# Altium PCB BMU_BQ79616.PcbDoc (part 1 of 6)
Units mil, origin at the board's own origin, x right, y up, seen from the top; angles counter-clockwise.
Board outline 7605 x 4005 mil, 4 copper layers (Top Layer, Layer 1, Layer 2, Bottom Layer), stack 37.446 mil thick; 709 components, 447 nets, 2028 pads, 1862 vias.
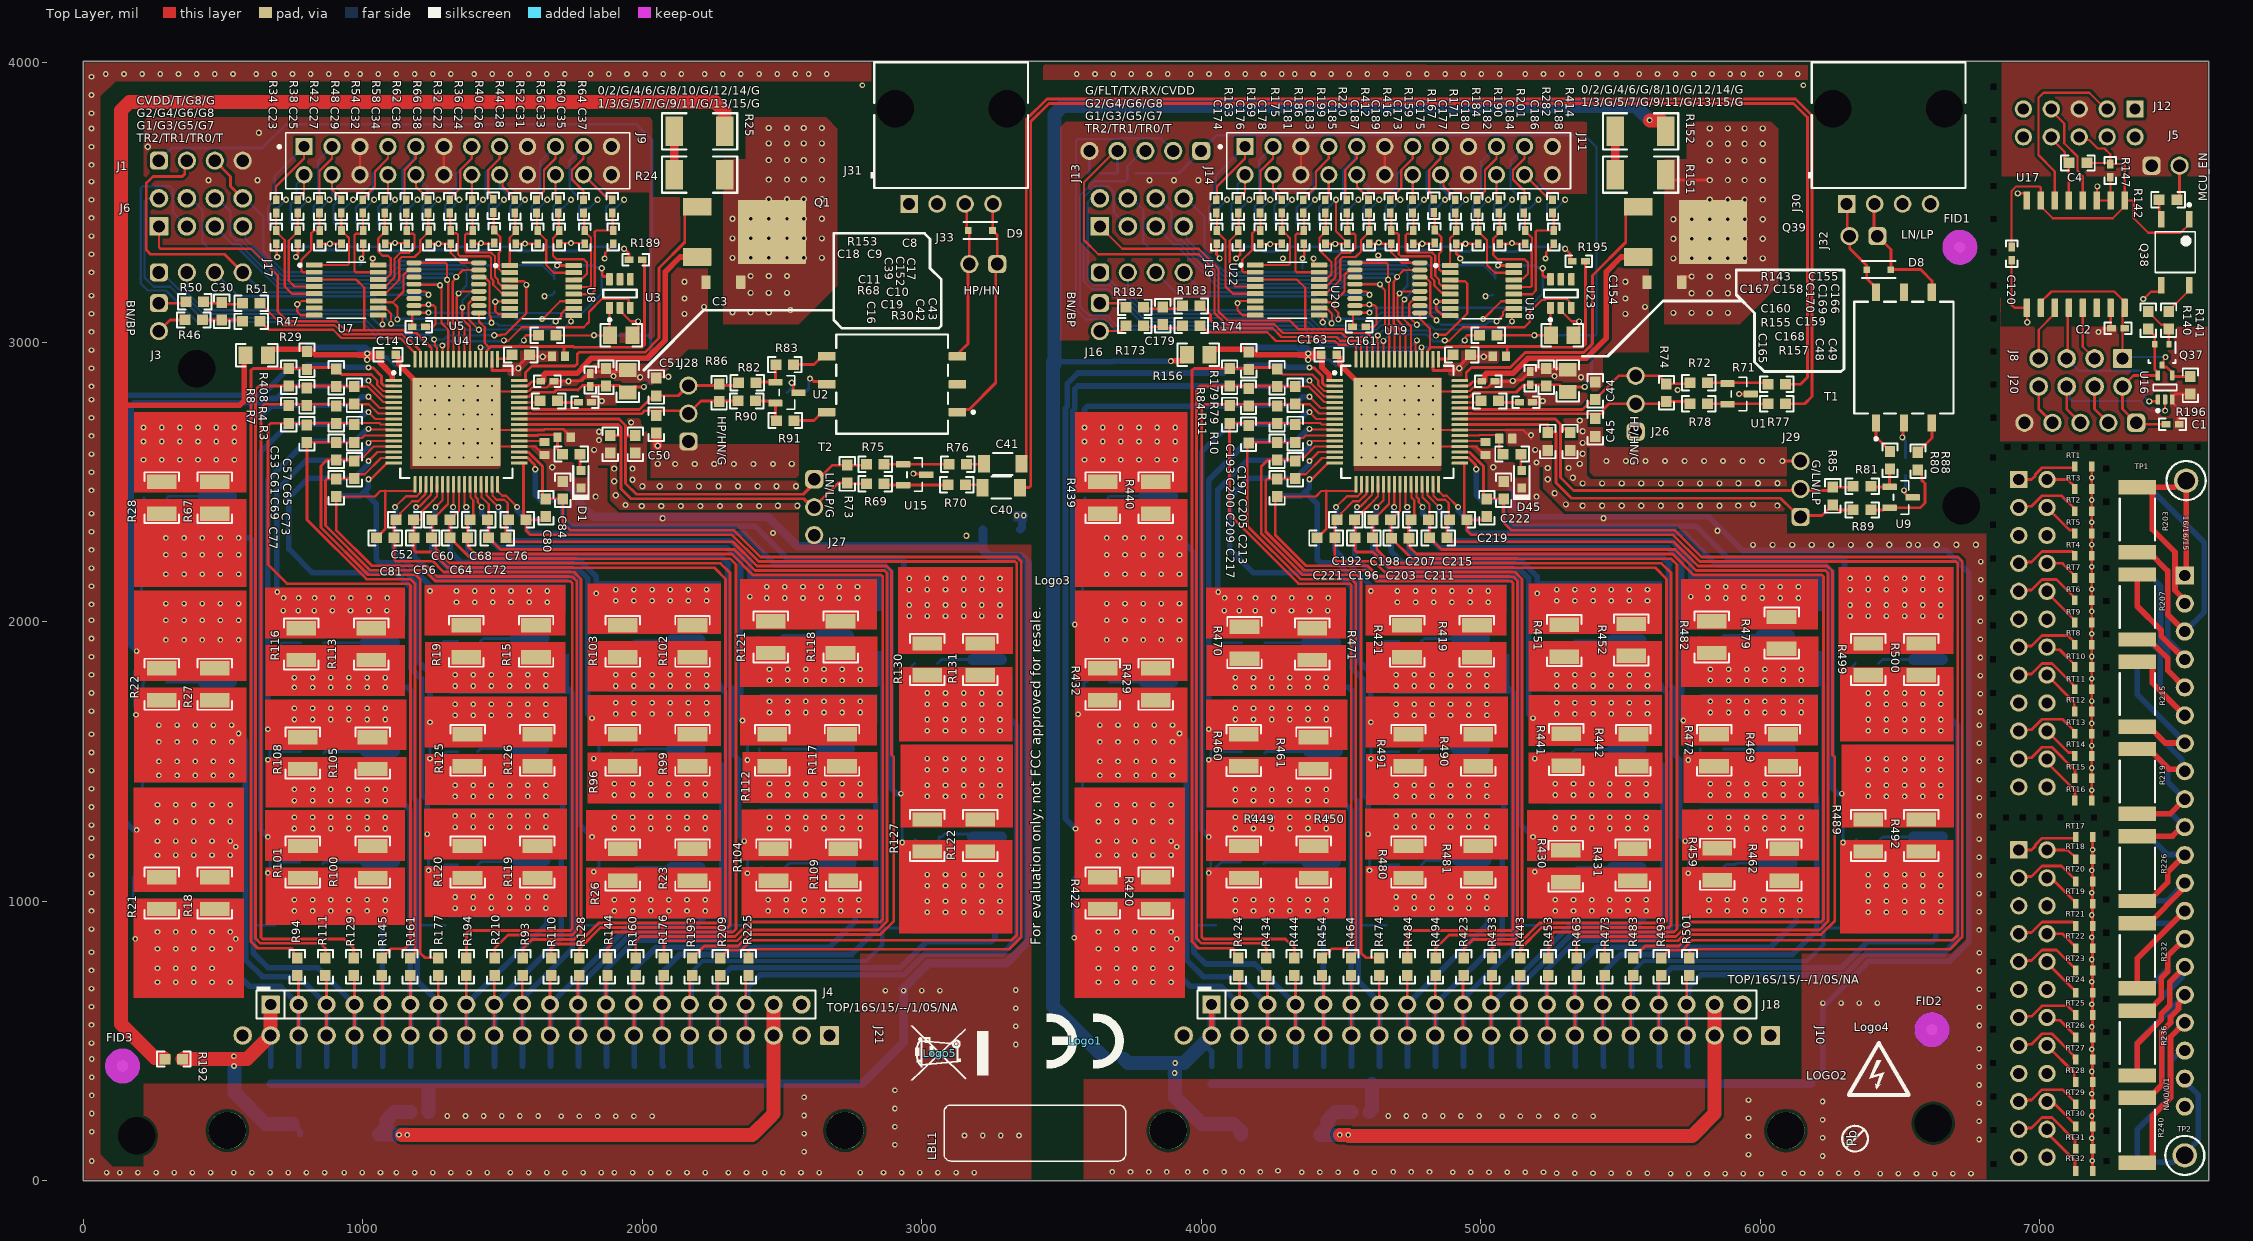
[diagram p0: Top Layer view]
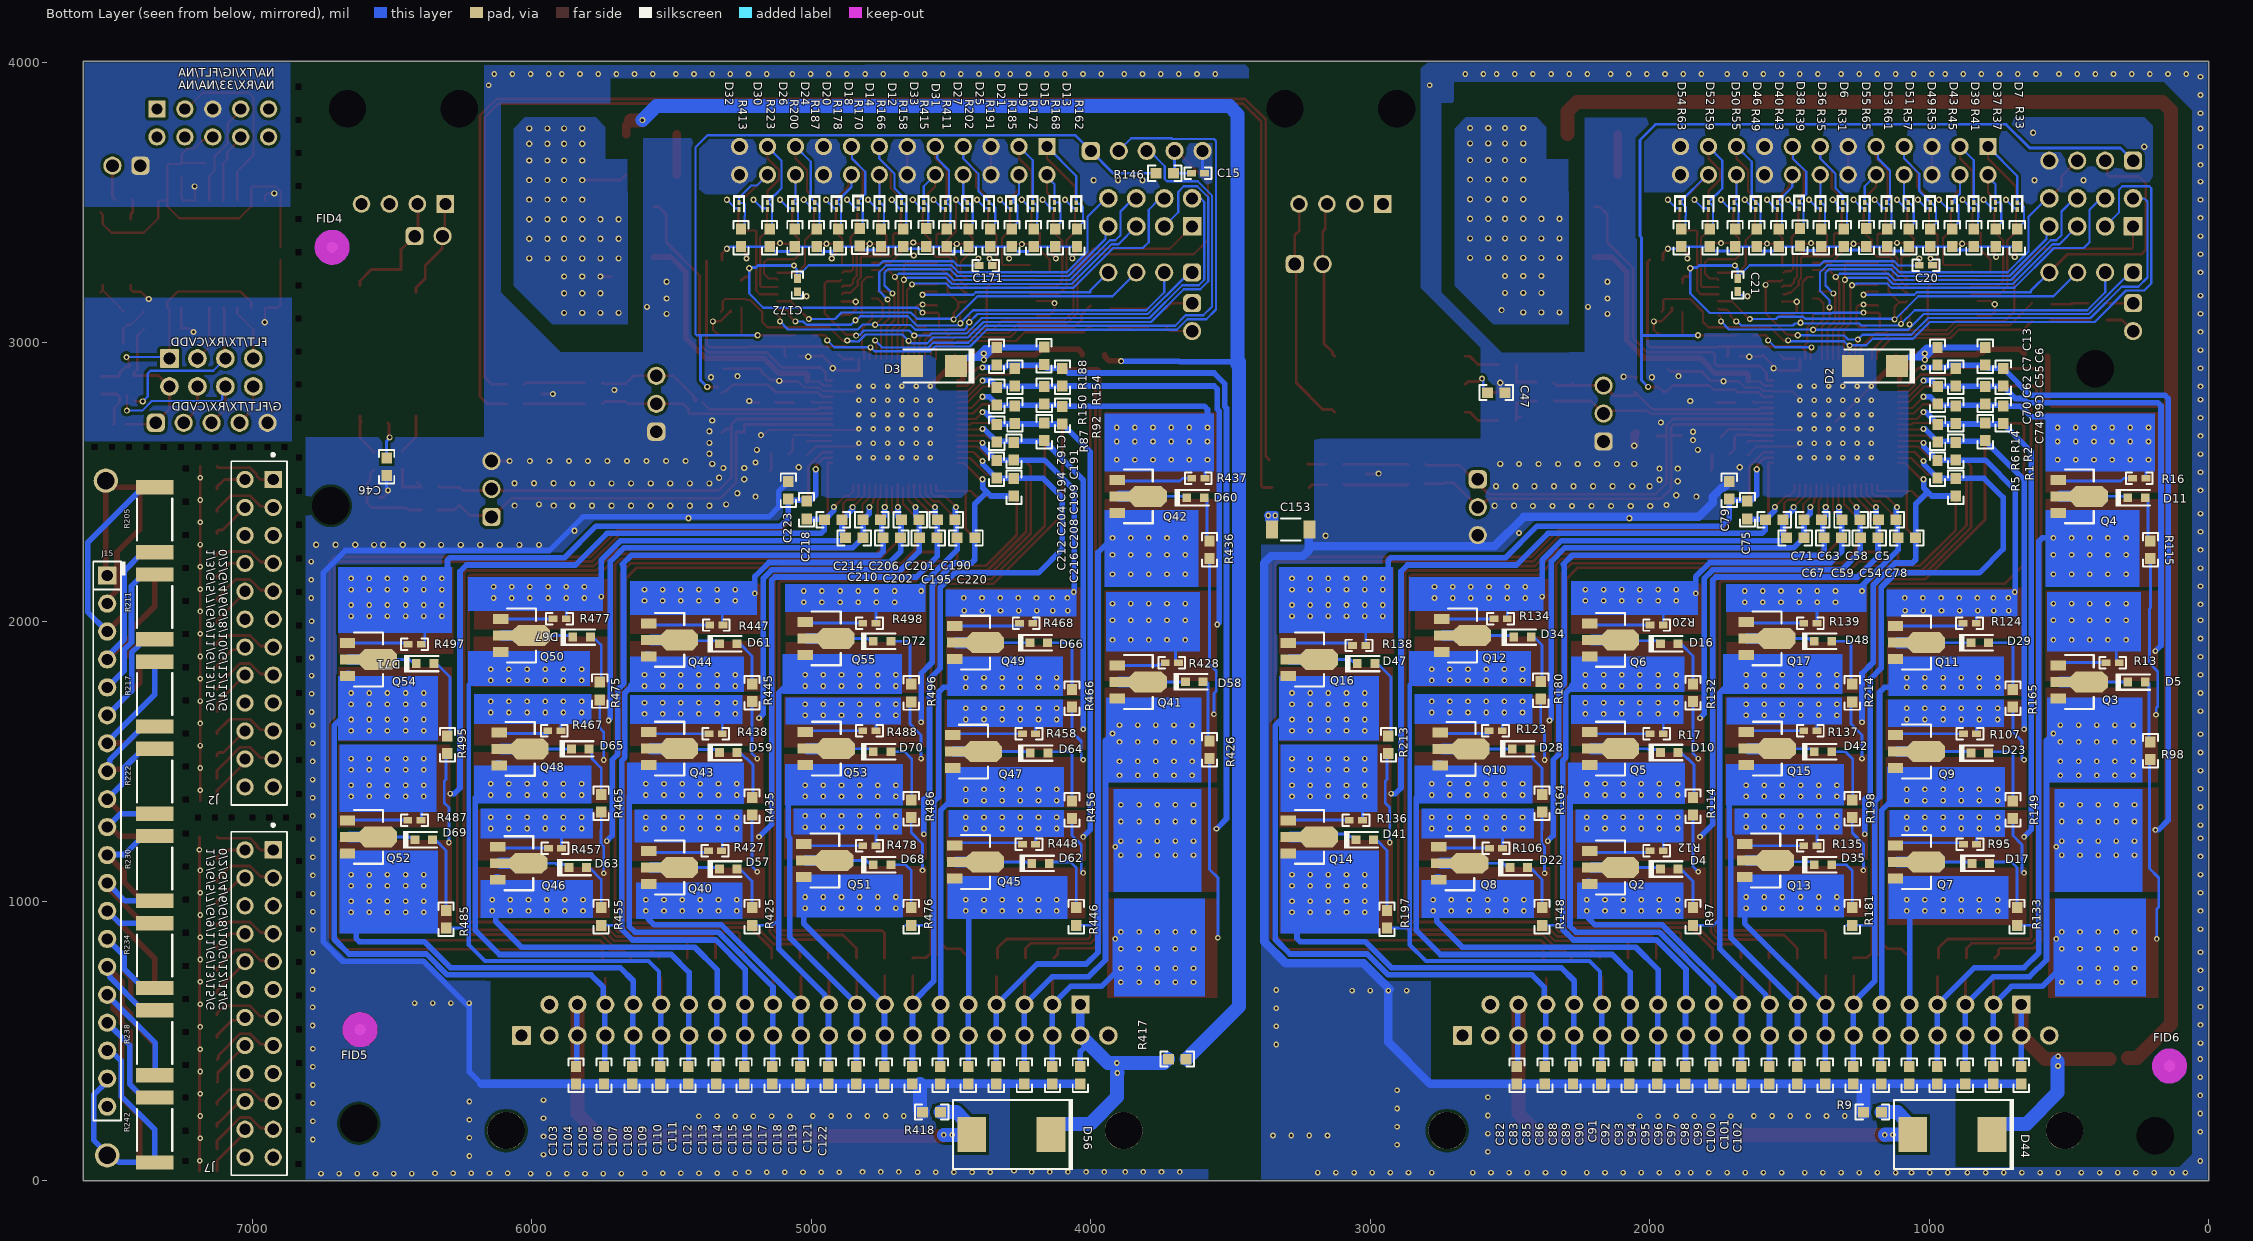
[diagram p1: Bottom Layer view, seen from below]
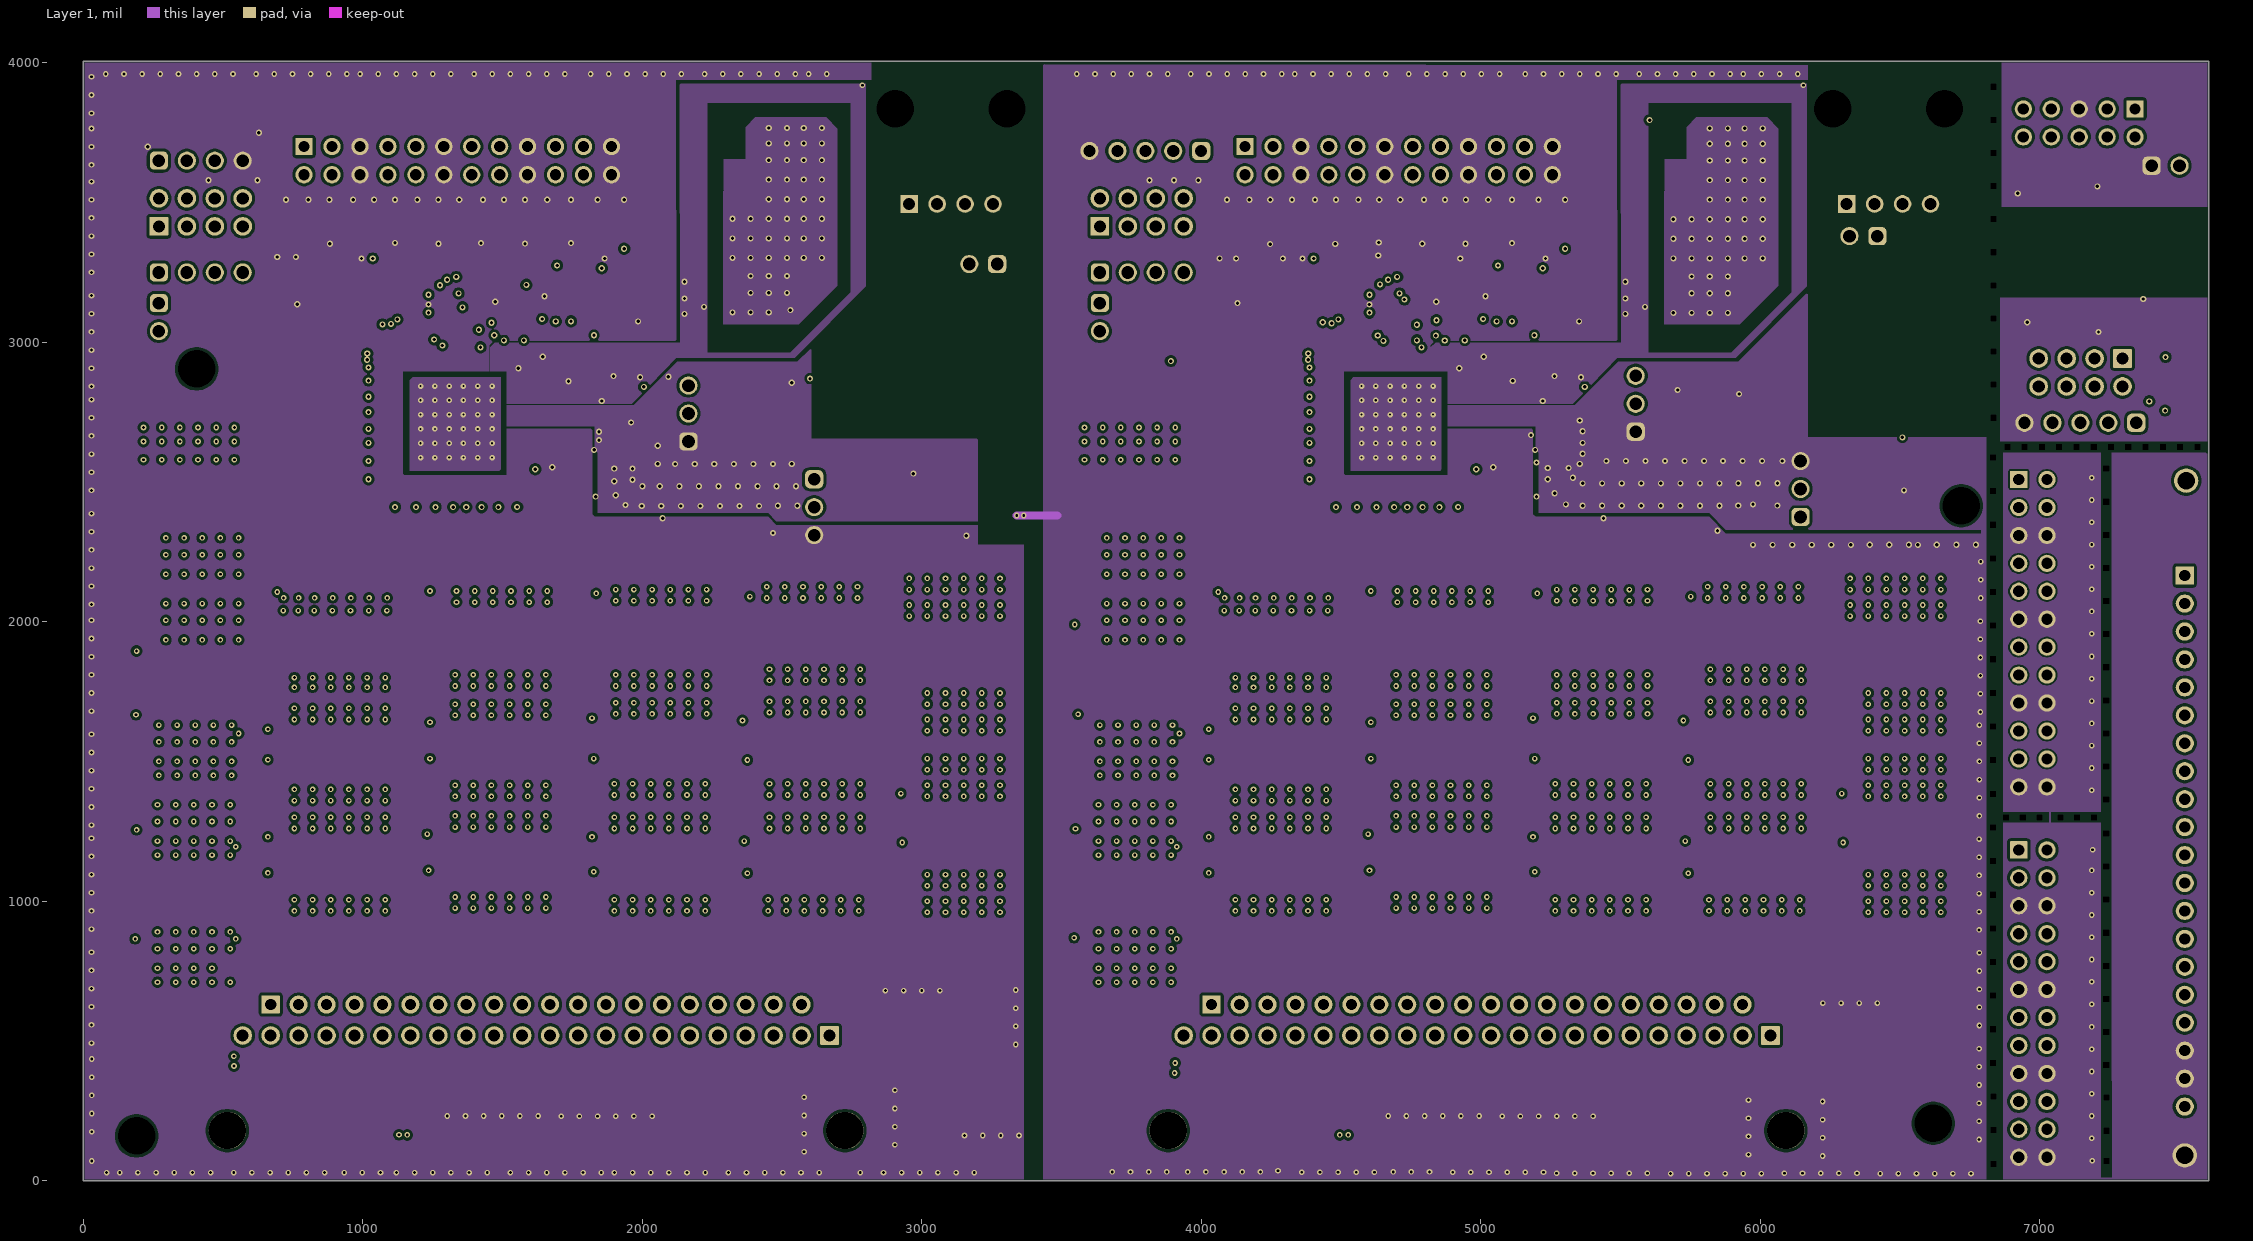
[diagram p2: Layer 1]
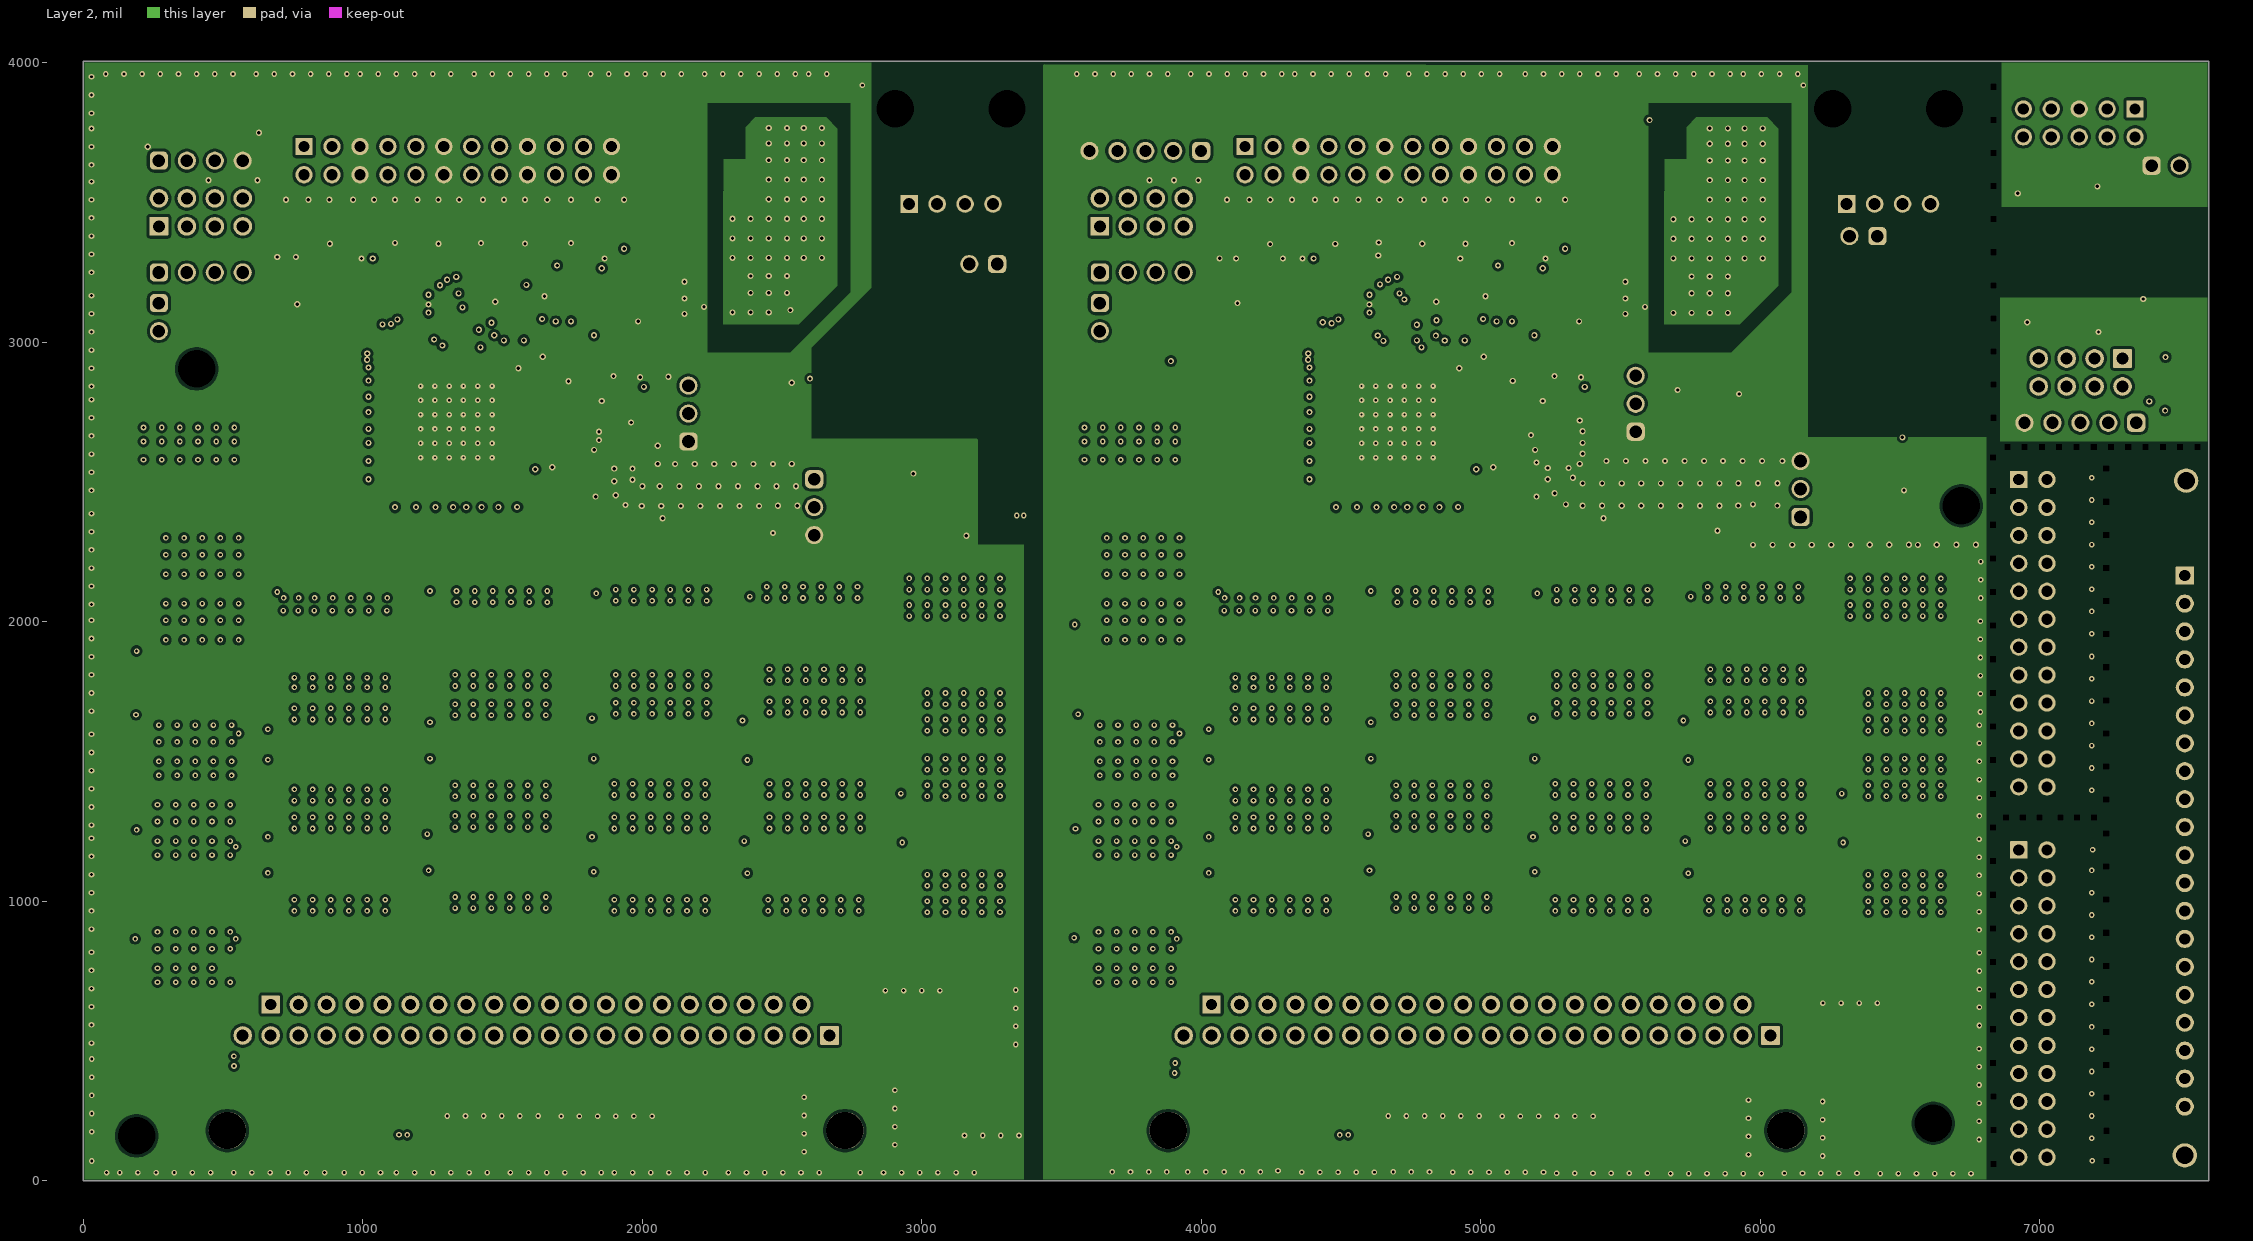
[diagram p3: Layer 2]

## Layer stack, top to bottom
Top Solder: solder mask 0.4, Solder Resist, Dk 3.5
Top Layer: signal copper 1.4
Dielectric 2: prepreg 6.693, PP-006, Dk 4.1
Layer 1: signal copper 1.378
Dielectric 1: prepreg 18.504, FR-4, Dk 4.8
Layer 2: signal copper 1.378
Dielectric 3: prepreg 6.693, PP-006, Dk 4.1
Bottom Layer: signal copper 1.4
Bottom Solder: solder mask 0.4, Solder Resist, Dk 3.5

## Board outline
6825,4005 7605,4005 7605,2640 7605,0 0,0 0,4005

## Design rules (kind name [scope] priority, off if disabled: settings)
AcuteAngle [All] p1: minimum=4.50000000000000E+0001 checktracksonly=FALSE
AssemblyTestPointUsage [All] p1: valid=2
BoardOutlineClearance BoardOutlineClearance_MountingHoles [OnCopper and InComponentClass('Mounting Holes')] p1: gap=39.37 ignorepadtopadclearanceinfootprint=FALSE
BoardOutlineClearance BoardOutlineClearance_Poly [OnCopper and IsPoly] p2: gap=3.94 ignorepadtopadclearanceinfootprint=FALSE
BoardOutlineClearance [OnCopper and Not InComponentClass('Logo') and not InComponentClass('FiducialMark') and not InRegion(1000,500,4000,800) and not InPoly] p3: gap=3.94 ignorepadtopadclearanceinfootprint=FALSE
Clearance Clearance_Fid [InComponent('FID1') or InComponent('FID2') or InComponent('FID3') or InComponent('FID4') or InComponent('FID5') or InComponent('FID6')] p1: gap=0 ignorepadtopadclearanceinfootprint=TRUE
Clearance Clearance_J2 [InComponent('J2')] p2: gap=6 ignorepadtopadclearanceinfootprint=TRUE
Clearance Clearance_Inner1 [OnLayer('Top Inner')] p3: gap=6 ignorepadtopadclearanceinfootprint=TRUE except(15: Arc-Fill Arc-Poly Arc-Region Track-Fill Track-Poly Track-Region SMDPad-Fill SMDPad-Poly SMDPad-Region THPad-Fill THPad-Poly THPad-Region Via-Fill Via-Poly Via-Region Fill-Fill Fill-Poly Fill-Region Poly-Poly Poly-Region Region-Region)
Clearance Clearance_Inner2 [OnLayer('Bottom Inner')] p4: gap=6 ignorepadtopadclearanceinfootprint=TRUE except(15: Arc-Fill Arc-Poly Arc-Region Track-Fill Track-Poly Track-Region SMDPad-Fill SMDPad-Poly SMDPad-Region THPad-Fill THPad-Poly THPad-Region Via-Fill Via-Poly Via-Region Fill-Fill Fill-Poly Fill-Region Poly-Poly Poly-Region Region-Region)
Clearance [All] p5: gap=6 ignorepadtopadclearanceinfootprint=TRUE except(10: Arc-Fill Arc-Poly Arc-Region Track-Fill Track-Poly Track-Region SMDPad-Fill SMDPad-Poly SMDPad-Region THPad-Fill THPad-Poly THPad-Region Via-Fill Via-Poly Via-Region Fill-Fill Fill-Poly Fill-Region Poly-Poly Poly-Region Region-Region)
ComponentClearance ComponentClearance_Header [InComponent('J17') or InComponent('J19') or InComponent('J23')] p1: gap=0.39 collisioncheckmode=3 verticalgap=0.39 showdistances=FALSE
ComponentClearance ComponentClearance_MountingHoles_FiducialMarks [InComponentClass('Mounting Holes') vs InComponentClass('FiducialMark')] p2: gap=50 collisioncheckmode=3 verticalgap=10 showdistances=FALSE
ComponentClearance ComponentClearance_Shunt [InComponentClass('Header') vs InComponentClass('Shunt')] p3: gap=0 collisioncheckmode=3 verticalgap=0 showdistances=FALSE
ComponentClearance ComponentClearance_Logo [InComponentClass('Logo')] p4: gap=50 collisioncheckmode=3 verticalgap=10 showdistances=FALSE
ComponentClearance ComponentClearance_ScrewToNut [(HasFootprint('NY PMS 440 0025 PH')) vs (HasFootprint('Keystone_1902C'))] p5: gap=5 collisioncheckmode=3 verticalgap=10 showdistances=FALSE
ComponentClearance ComponentClearance_MountingHoles [InComponentClass('Mounting Holes')] p6: gap=250 collisioncheckmode=3 verticalgap=100000 showdistances=FALSE
ComponentClearance ComponentClearance_SmallPassives [HasFootprint('0201*') or HasFootprint('0402*') or HasFootprint('0508') or HasFootprint('0603*') or HasFootprint('0612') or HasFootprint('0805*') or HasFootprint('0815*') or HasFootprint('0830*') or HasFootprint('1206*') or HasFootprint('1210*') or HasFootprint('1808*') or HasFootprint('1812*') or HasFootprint('1825*') or HasFootprint('2010*') or HasFootprint('2220*') or HasFootprint('2225*') or HasFootprint('2512*') or HasFootprint('2728*') or HasFootprint('3518*') vs HasFootprint('0201*') or HasFootprint('0402*') or HasFootprint('0508') or HasFootprint('0603*') or HasFootprint('0612') or HasFootprint('0805*') or HasFootprint('0815*') or HasFootprint('0830*') or HasFootprint('1206*') or HasFootprint('1210*') or HasFootprint('1808*') or HasFootprint('1812*') or HasFootprint('1825*') or HasFootprint('2010*') or HasFootprint('2220*') or HasFootprint('2225*') or HasFootprint('2512*') or HasFootprint('2728*') or HasFootprint('3518*')] p7: gap=0.39 collisioncheckmode=3 verticalgap=10 showdistances=FALSE
ComponentClearance ComponentClearance_THtoSMT [IsThruComponent vs IsSMTComponent] p8: gap=40 collisioncheckmode=3 verticalgap=30 showdistances=FALSE
ComponentClearance ComponentClearance_THtoTH [IsThruComponent vs IsThruComponent] p9: gap=30 collisioncheckmode=3 verticalgap=30 showdistances=FALSE
ComponentClearance [All] p10: gap=0 collisioncheckmode=3 verticalgap=10 showdistances=FALSE
DiffPairsRouting [All] p1: maxlimit=100 minlimit=10 mostfreqgap=10 toplayer_minwidth=7.87 toplayer_maxwidth=15 toplayer_prefwidth=10 midlayer1_minwidth=7.87 midlayer1_maxwidth=15 midlayer1_prefwidth=10 midlayer2_minwidth=7.87 midlayer2_maxwidth=15 midlayer2_prefwidth=10 bottomlayer_minwidth=7.87 bottomlayer_maxwidth=15 bottomlayer_prefwidth=10 maxuncoupledlength=1000
FabricationTestPointUsage TestPointUsage [All] p1: valid=2 allowmultiple=FALSE
FabricationTestpoint Testpoint [All] p1: side=3 testpointundercomponent=TRUE minsize=40 maxsize=100 preferedsize=60 minholesize=0 maxholesize=40 preferedholesize=32 testpointgrid=1 allowsidetop=TRUE allowsidebottom=TRUE usegrid=TRUE gridtolerance=0.01
FanoutControl Fanout_LCC [IsLCC] p1: bgadir=Out bgaviamode=Centered fanoutstyle=Auto fanoutdirection=Alternating viagrid=1 // Fanout_LCC (Default Rule)
FanoutControl Fanout_BGA [IsBGA] p2: bgadir=Out bgaviamode=Centered fanoutstyle=Auto fanoutdirection=Alternating viagrid=1 // Fanout_BGA (Default Rule)
FanoutControl Fanout_Default [All] p4: bgadir=Out bgaviamode=Centered fanoutstyle=Auto fanoutdirection=Alternating viagrid=1 // Fanout_Default (Default Rule)
FanoutControl Fanout_Small [(CompPinCount < 5)] p5: bgadir=Out bgaviamode=Centered fanoutstyle=Auto fanoutdirection=OutThenIn viagrid=1 // Fanout_Small (Default Rule)
Height [All] p1: minheight=0 maxheight=2048 prefheight=500
HoleSize [All] p1: absolutevalues=TRUE maxlimit=251 minlimit=7.87 maxpercent=80.000 minpercent=20.000
HoleToHoleClearance [All] p1: gap=7.87 allowstackedmicrovias=TRUE
MinimumAnnularRing MinimumAnnularRing_ThermalPadVias [IsVia and InAnyComponent] p1: minimumring=2
MinimumAnnularRing [All] p2: minimumring=3.94
MinimumSolderMaskSliver MinimumSolderMaskSliver_Logo [InComponentClass('Logo') vs InComponentClass('Logo')] p1: minsoldermaskwidth=0.7
MinimumSolderMaskSliver [All] p2: minsoldermaskwidth=0.39
PlaneConnect [All] p1: planeconnectstyle=Relief reliefexpansion=10 reliefentries=4 reliefconductorwidth=10 reliefairgap=10
PolygonConnect [All] p1: connectstyle=Direct reliefconductorwidth=10 reliefentries=4 polygonreliefangle="90 Angle" airgapwidth=10
RoutingVias ThermalPadVias [IsVia and InAnyComponent] p1: holewidth=7.87 width=19.68 viastyle="Through Hole" minholewidth=7.87 minwidth=11.81 maxholewidth=19.68 maxwidth=27.56
RoutingVias [All] p2: holewidth=16 width=34 viastyle="Through Hole" minholewidth=7.87 minwidth=15 maxholewidth=40 maxwidth=65
SilkToSilkClearance SilkToSilkClearance_Pb-FreeLogo [(HasFootprint('Pb-Free_Overlay_Medium') OR HasFootprint('Pb-Free_Overlay_Small')) vs (HasFootprint('Pb-Free_Overlay_Medium') OR HasFootprint('Pb-Free_Overlay_Small'))] p1: silktosilkclearance=0
SilkToSilkClearance [All] p2: silktosilkclearance=0.39
SilkToSolderMaskClearance SilkToComponentPadClearance [(IsPad or IsFill or IsRegion) and InAnycomponent] p1: minsilkscreentomaskgap=0 clearancetoexposedcopper=TRUE
SilkToSolderMaskClearance "Silk to Solder Mask Opening" [All] p2: minsilkscreentomaskgap=0 clearancetoexposedcopper=FALSE
SolderMaskExpansion [All] p1: expansion=1.97 istentingtop=FALSE
UnRoutedNet [All] p1: checkbadconnections=TRUE
Width [All] p1: maxlimit=100 minlimit=99999 preferedwidth=10 toplayer_minwidth=0 midlayer1_minwidth=0 midlayer2_minwidth=0 bottomlayer_minwidth=0 minimp=50.000000 maximp=50.000000 favimp=50.000000 checkconnectedcopper=TRUE
13 further rules are at their usual default settings.

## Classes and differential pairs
component class U_Cell_Simulator: J2 J7 J15 R203 R205 R207 R211 R215 R217 R219 R222 R226 R230 R232 R234 R236 R238 R240 R242 RT1 RT2 RT3 RT4 RT5 RT6 RT7 RT8 RT9 RT10 RT11 RT12 RT13 RT14 RT15 RT16 RT17 RT18 RT19 RT20 RT21 RT22 RT23 RT24 RT25 RT26 RT27 RT28 RT29 RT30 RT31 RT32 TP1 TP2
component class "Transf_Daisy Chain Isolation": C46 C47 C48 C49 C50 C51 D8 D9 J28 J29 J30 J31 J32 J33 R80 R81 R82 R83 R85 R86 R88 R89 R90 R91 T1 T2 U2 U9
component class Label: LBL1
component class Header: J1 J3 J4 J5 J13 J15 J16 J17 J18 J19 J20 J26 J27 J28 J29 J32 J33
component class Hardware: !PCB1 FID1 FID2 FID3 FID4 FID5 FID6 H9 H10 H11 LBL1 LOGO2 Logo3 Logo4
component class FiducialMark: FID1 FID2 FID3 FID4 FID5 FID6
component class Cell_Network_A2: C5 C6 C7 C52 C53 C54 C55 C56 C57 C58 C59 C60 C61 C62 C63 C64 C65 C66 C67 C68 C69 C70 C71 C72 C73 C74 C75 C76 C77 C78 C79 C80 C81 C82 C83 C84 C85 C86 C88 C89 C90 C91 C92 C93 C94 C95 C96 C97 C98 C99 C100 C101 C102 D4 D5 D10 D11 D16 D17 D22 D23 D28 D29 D34 D35 D41 D42 D44 D47 D48 J3 J4 J21 Q2 Q3 Q4 Q5 Q6 Q7 Q8 Q9 Q10 Q11 Q12 Q13 Q14 Q15 Q16 Q17 R9 R12 R13 R15 R16 R17 R18 R19 R20 R21 R22 R23 R26 R27 R28 R67 R93 R94 R95 R96 R97 R98 R99 R100 R101 R102 R103 R104 R105 R106 R107 R108 R109 R110 R111 R112 R113 R114 R115 R116 R117 R118 R119 R120 R121 R122 R123 R124 R125 R126 R127 R128 R129 R130 R131 R132 R133 R134 R135 R136 R137 R138 R139 R144 R145 R148 R149 R160 R161 R164 R165 R176 R177 R180 R181 R192 R193 R194 R197 R198 R209 R210 R213 R214 R225
component class Cell_Network_A1: C103 C104 C105 C106 C107 C108 C109 C110 C111 C112 C113 C114 C115 C116 C117 C118 C119 C121 C122 C190 C191 C192 C193 C194 C195 C196 C197 C198 C199 C200 C201 C202 C203 C204 C205 C206 C207 C208 C209 C210 C211 C212 C213 C214 C215 C216 C217 C218 C219 C220 C221 C222 C223 D56 D57 D58 D59 D60 D61 D62 D63 D64 D65 D66 D67 D68 D69 D70 D71 D72 J10 J16 J18 Q40 Q41 Q42 Q43 Q44 Q45 Q46 Q47 Q48 Q49 Q50 Q51 Q52 Q53 Q54 Q55 R417 R418 R419 R420 R421 R422 R423 R424 R425 R426 R427 R428 R429 R430 R431 R432 R433 R434 R435 R436 R437 R438 R439 R440 R441 R442 R443 R444 R445 R446 R447 R448 R449 R450 R451 R452 R453 R454 R455 R456 R457 R458 R459 R460 R461 R462 R463 R464 R465 R466 R467 R468 R469 R470 R471 R472 R473 R474 R475 R476 R477 R478 R479 R480 R481 R482 R483 R484 R485 R486 R487 R488 R489 R490 R491 R492 R493 R494 R495 R496 R497 R498 R499 R500 R501
component class "Cap_Daisy Chain Isolation": C40 C41 C42 C43 C44 C45 C153 J26 J27 R69 R70 R71 R72 R73 R74 R75 R76 R77 R78 U1 U15
component class bq79616_A2: C3 C8 C9 C10 C11 C12 C13 C14 C16 C17 C18 C19 C20 C21 C22 C23 C24 C25 C26 C27 C28 C29 C30 C31 C32 C33 C34 C35 C36 C37 C38 C39 C152 D1 D2 D6 D7 D36 D37 D38 D39 D40 D43 D46 D49 D50 D51 D52 D53 D54 D55 J1 J6 J9 J17 Q1 R1 R2 R3 R4 R5 R6 R7 R8 R14 R24 R25 R29 R30 R31 R32 R33 R34 R35 R36 R37 R38 R39 R40 R41 R42 R43 R44 R45 R46 R47 R48 R49 R50 R51 R52 R53 R54 R55 R56 R57 R58 R59 R60 R61 R62 R63 R64 R65 R66 R68 R153 R189 R408 U3 U4 U5 U7 U8
component class bq79616_A1: C1 C2 C4 C15 C120 C154 C155 C158 C159 C160 C161 C162 C163 C165 C166 C167 C168 C169 C170 C171 C172 C173 C174 C175 C176 C177 C178 C179 C180 C181 C182 C183 C184 C185 C186 C187 C188 C189 D3 D12 D13 D14 D15 D18 D19 D20 D21 D24 D25 D26 D27 D30 D31 D32 D33 D45 J5 J8 J11 J12 J13 J14 J19 J20 Q37 Q38 Q39 R10 R11 R79 R84 R87 R92 R140 R141 R142 R143 R146 R147 R150 R151 R152 R154 R155 R156 R157 R158 R159 R162 R163 R166 R167 R168 R169 R170 R171 R172 R173 R174 R175 R178 R179 R182 R183 R184 R185 R186 R187 R188 R190 R191 R195 R196 R199 R200 R201 R202 R220 R223 R282 R411 R412 R413 R414 R415 R416 U16 U17 U18 U19 U20 U22 U23

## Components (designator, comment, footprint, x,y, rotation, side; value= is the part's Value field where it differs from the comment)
C1 "GCM155R71A104KA55D" 0402 7476.24,2706.97 r180 top value=0.1uF
C2 "GCM155R71A104KA55D" 0402 7281.24,3049.97 r180 top value=0.1uF
C3 "GCM31MR72A224KA37L" FP-GCM31MR72A224KA37L_1206-MFG 2290,3215 r0 top
C4 "GCM155R71A104KA55D" 0402 7253.24,3614.59 r90 top value=0.1uF
C5 "GCM188R71C474KA55D" 0603 1149.41,2365 r0 bottom value=0.47uF
C6 "GCM188R71C474KA55D" 0603 904.41,2875 r270 bottom value=0.47uF
C7 "GCM188R71C474KA55D" 0603 969.41,2810 r270 bottom value=0.47uF
C8 "GRM21BR71C105KA01L" 0805_HV 1925,3025 r0 top value=1uF
C9 "C0603C105K8RACAUTO" "FP-C0603C105K8RACAUTO_0603 (1608 Metric)-MFG" 1700,2950 r180 top
C10 "GCM155R71A104KA55D" 0402 1795,2785 r180 top value=0.1uF
C11 "GCM155R71A104KA55D" 0402 1660,2860 r180 top value=0.1uF
C12 "GCM155R71H104KE02D" 0402 1200,3055 r180 top value=0.1uF
C13 "GCM188R71C474KA55D" 0603 969.93,2950 r90 bottom value=0.47uF
C14 "GCM188R72A103KA37J" 0603_HV 1090,2955 r0 top value=0.01uF
C15 "GCM155R71A104KA55D" 0402 3616.38,3605 r0 bottom value=0.1uF
C16 "C0603C105K8RACAUTO" "FP-C0603C105K8RACAUTO_0603 (1608 Metric)-MFG" 1650,2620 r90 top
C17 "C2012X7R1A475M125AC" 0805_HV 1948,2860 r90 top value=4.7uF
C18 "C0603C225K8PACTU" 0603 1565,2955 r180 top value=2.2uF
C19 "C0603C105K8RACAUTO" "FP-C0603C105K8RACAUTO_0603 (1608 Metric)-MFG" 1720,2660 r180 top
C20 "GCM155R71H104KE02D" 0402 1011.38,3275 r180 bottom value=0.1uF
C21 "GCM155R71H104KE02D" 0402 1685,3205 r270 bottom value=0.1uF
C22 "GCM155R71H104KE02D" 0402 1314.41,3376.38 r270 top value=0.1uF
C23 "GCM155R71H104KE02D" 0402 689.41,3376.38 r270 top value=0.1uF
C24 "GCM155R71H104KE02D" 0402 1393.41,3376.38 r270 top value=0.1uF
C25 "GCM155R71H104KE02D" 0402 767.41,3376.38 r270 top value=0.1uF
C26 "GCM155R71H104KE02D" 0402 1470,3378.62 r270 top value=0.1uF
C27 "GCM155R71H104KE02D" 0402 845.41,3376.38 r270 top value=0.1uF
C28 "GCM155R71H104KE02D" 0402 1547.41,3376.38 r270 top value=0.1uF
C29 "GCM155R71H104KE02D" 0402 923.41,3376.38 r270 top value=0.1uF
C30 "GCM188R71C474KA55D" 0603 495,3111.5 r90 top value=0.47uF
C31 "GCM155R71H104KE02D" 0402 1625.41,3376.38 r270 top value=0.1uF
C32 "GCM155R71H104KE02D" 0402 1001.41,3376.38 r270 top value=0.1uF
C33 "GCM155R71H104KE02D" 0402 1703.41,3376.38 r270 top value=0.1uF
C34 "GCM155R71H104KE02D" 0402 1079.41,3376.38 r270 top value=0.1uF
C35 "GCM155R71H104KE02D" 0402 1794.41,3376.38 r270 top value=0.1uF
C36 "GCM155R71H104KE02D" 0402 1157.41,3376.38 r270 top value=0.1uF
C37 "GCM155R71H104KE02D" 0402 1896.41,3376.38 r270 top value=0.1uF
C38 "GCM155R71H104KE02D" 0402 1235.41,3376.38 r270 top value=0.1uF
C39 "GCM155R71A104KA55D" 0402 1813,2865 r270 top value=0.1uF
C40 "1206J2K00222KXR" 1206_180 3285,2480 r0 top value=2200pF
C41 "1206J2K00222KXR" 1206_180 3290,2565 r0 top value=2200pF
C42 "CL10B221JB8NNNC" 0603 1885,2635 r270 top value=220pF
C43 "CL10B221JB8NNNC" 0603 1975,2635 r270 top value=220pF
C44 "CL10B221JB8NNNC" 0603 5410,2826.5 r90 top value=220pF
C45 "CL10B221JB8NNNC" 0603 5410,2695 r270 top value=220pF
C46 "GCM1885C1H101JA16J" 0603 6520,2555 r270 bottom value=100pF
C47 "GCM1885C1H101JA16J" 0603 2549.41,2820 r180 bottom value=100pF
C48 "CL10B221JB8NNNC" 0603 5240,2645 r270 top value=220pF
C49 "CL10B221JB8NNNC" 0603 5320,2645 r270 top value=220pF
C50 "CL10B221JB8NNNC" 0603 2050,2706.5 r270 top value=220pF
C51 "CL10B221JB8NNNC" 0603 2050,2840 r90 top value=220pF
C52 "GCM188R71C474KA55D" 0603 1149.41,2365 r0 top value=0.47uF
C53 "GCM188R71C474KA55D" 0603 904.41,2873.5 r270 top value=0.47uF
C54 "GCM188R71C474KA55D" 0603 1214.41,2300 r0 bottom value=0.47uF
C55 "GCM188R71C474KA55D" 0603 904.41,2740 r270 bottom value=0.47uF
C56 "GCM188R71C474KA55D" 0603 1214.41,2300 r0 top value=0.47uF
C57 "GCM188R71C474KA55D" 0603 969.41,2810 r270 top value=0.47uF
C58 "GCM188R71C474KA55D" 0603 1279.41,2365 r0 bottom value=0.47uF
C59 "GCM188R71C474KA55D" 0603 1344.41,2300 r0 bottom value=0.47uF
C60 "GCM188R71C474KA55D" 0603 1279.41,2365 r0 top value=0.47uF
C61 "GCM188R71C474KA55D" 0603 904.41,2740 r270 top value=0.47uF
C62 "GCM188R71C474KA55D" 0603 969.41,2675 r270 bottom value=0.47uF
C63 "GCM188R71C474KA55D" 0603 1415.91,2365 r0 bottom value=0.47uF
C64 "GCM188R71C474KA55D" 0603 1342.91,2300 r0 top value=0.47uF
C65 "GCM188R71C474KA55D" 0603 969.41,2673.5 r270 top value=0.47uF
C66 "GCM188R71C474KA55D" 0603 904.41,2610 r270 bottom value=0.47uF
C67 "GCM188R71C474KA55D" 0603 1479.41,2300 r0 bottom value=0.47uF
C68 "GCM188R71C474KA55D" 0603 1414.41,2365 r0 top value=0.47uF
C69 "GCM188R71C474KA55D" 0603 904.41,2610 r270 top value=0.47uF
C70 "GCM188R71C474KA55D" 0603 970,2545 r270 bottom value=0.47uF
C71 "GCM188R71C474KA55D" 0603 1554.41,2365 r0 bottom value=0.47uF
C72 "GCM188R71C474KA55D" 0603 1480.91,2300 r0 top value=0.47uF
C73 "GCM188R71C474KA55D" 0603 969.41,2543.5 r270 top value=0.47uF
C74 "GCM188R71C474KA55D" 0603 904.41,2481.5 r270 bottom value=0.47uF
C75 "GCM188R71C474KA55D" 0603 1650,2400 r90 bottom value=0.47uF
C76 "GCM188R71C474KA55D" 0603 1552.91,2365 r0 top value=0.47uF
C77 "GCM188R71C474KA55D" 0603 904.41,2480 r270 top value=0.47uF
C78 "GCM188R71C474KA55D" 0603 1079.41,2300 r0 bottom value=0.47uF
C79 "GCM188R71C474KA55D" 0603 1715,2470 r90 bottom value=0.47uF
C80 "GCM188R71C474KA55D" 0603 1655,2408.5 r90 top value=0.47uF
C81 "GCM188R71C474KA55D" 0603 1079.41,2300 r0 top value=0.47uF
C82 "885012206114" 0603 2475,377.36 r270 bottom value=0.01uF
C83 "885012206114" 0603 2374.72,377.36 r270 bottom value=0.01uF
C84 "GCM188R71C474KA55D" 0603 1715,2470 r90 top value=0.47uF
C85 "885012206114" 0603 2274.44,377.36 r270 bottom value=0.01uF
C86 "885012206114" 0603 2174.17,377.36 r270 bottom value=0.01uF
C88 "885012206114" 0603 2073.89,377.36 r270 bottom value=0.01uF
C89 "885012206114" 0603 1973.61,377.36 r270 bottom value=0.01uF
C90 "885012206114" 0603 1873.33,377.36 r270 bottom value=0.01uF
C91 "885012206114" 0603 1773.05,377.36 r270 bottom value=0.01uF
C92 "885012206114" 0603 1672.78,377.36 r270 bottom value=0.01uF
C93 "885012206114" 0603 1572.5,377.36 r270 bottom value=0.01uF
C94 "885012206114" 0603 1472.22,377.36 r270 bottom value=0.01uF
C95 "885012206114" 0603 1371.94,377.36 r270 bottom value=0.01uF
C96 "885012206114" 0603 1271.67,377.36 r270 bottom value=0.01uF
C97 "885012206114" 0603 1171.39,377.36 r270 bottom value=0.01uF
C98 "885012206114" 0603 1071.11,377.36 r270 bottom value=0.01uF
C99 "885012206114" 0603 970.83,377.36 r270 bottom value=0.01uF
C100 "885012206114" 0603 870.56,377.36 r270 bottom value=0.01uF
C101 "885012206114" 0603 770.28,377.36 r270 bottom value=0.01uF
C102 "885012206114" 0603 670,377.36 r270 bottom value=0.01uF
C103 "885012206114" 0603 5842.36,377.36 r270 bottom value=0.01uF
C104 "885012206114" 0603 5742.08,377.36 r270 bottom value=0.01uF
C105 "885012206114" 0603 5641.81,377.36 r270 bottom value=0.01uF
C106 "885012206114" 0603 5541.53,377.36 r270 bottom value=0.01uF
C107 "885012206114" 0603 5441.25,377.36 r270 bottom value=0.01uF
C108 "885012206114" 0603 5340.97,377.36 r270 bottom value=0.01uF
C109 "885012206114" 0603 5240.69,377.36 r270 bottom value=0.01uF
C110 "885012206114" 0603 5140.42,377.36 r270 bottom value=0.01uF
C111 "885012206114" 0603 5040.14,377.36 r270 bottom value=0.01uF
C112 "885012206114" 0603 4939.86,377.36 r270 bottom value=0.01uF
C113 "885012206114" 0603 4839.58,377.36 r270 bottom value=0.01uF
C114 "885012206114" 0603 4739.31,377.36 r270 bottom value=0.01uF
C115 "885012206114" 0603 4639.03,377.36 r270 bottom value=0.01uF
C116 "885012206114" 0603 4538.75,377.36 r270 bottom value=0.01uF
C117 "885012206114" 0603 4438.47,377.36 r270 bottom value=0.01uF
C118 "885012206114" 0603 4338.2,377.36 r270 bottom value=0.01uF
C119 "885012206114" 0603 4237.92,377.36 r270 bottom value=0.01uF
C120 "GCM155R71A104KA55D" 0402 6900.24,3316.97 r90 top value=0.1uF
C121 "885012206114" 0603 4137.36,377.36 r270 bottom value=0.01uF
C122 "885012206114" 0603 4037.36,377.36 r270 bottom value=0.01uF
C152 "CGA3E2X7R2A223K080AA" 0603 1870,2875 r90 top value=0.022uF
C153 "1206J2K00222KXR" 1206_180 3285,2330 r0 bottom value=2200pF
C154 "GCM31MR72A224KA37L" FP-GCM31MR72A224KA37L_1206-MFG 5657.36,3215 r0 top
C155 "GRM21BR71C105KA01L" 0805_HV 5292.36,3025 r0 top value=1uF
C158 "C0603C105K8RACAUTO" "FP-C0603C105K8RACAUTO_0603 (1608 Metric)-MFG" 5067.36,2950 r180 top
C159 "GCM155R71A104KA55D" 0402 5162.36,2785 r180 top value=0.1uF
C160 "GCM155R71A104KA55D" 0402 5027.36,2860 r180 top value=0.1uF
C161 "GCM155R71H104KE02D" 0402 4565.39,3055 r180 top value=0.1uF
C162 "GCM188R71C474KA55D" 0603 4337.3,2950 r90 bottom value=0.47uF
C163 "GCM188R72A103KA37J" 0603_HV 4457.36,2955 r0 top value=0.01uF
C165 "C0603C105K8RACAUTO" "FP-C0603C105K8RACAUTO_0603 (1608 Metric)-MFG" 5017.36,2620 r90 top
C166 "C2012X7R1A475M125AC" 0805_HV 5312.36,2861.69 r90 top value=4.7uF
C167 "C0603C225K8PACTU" 0603 4932.36,2955 r180 top value=2.2uF
C168 "C0603C105K8RACAUTO" "FP-C0603C105K8RACAUTO_0603 (1608 Metric)-MFG" 5090,2655 r180 top
C169 "CGA3E2X7R2A223K080AA" 0603 5235,2875 r90 top value=0.022uF
C170 "GCM155R71A104KA55D" 0402 5177.36,2871.38 r270 top value=0.1uF
C171 "GCM155R71H104KE02D" 0402 4376.16,3274.78 r180 bottom value=0.1uF
C172 "GCM155R71H104KE02D" 0402 5049.78,3204.78 r270 bottom value=0.1uF
C173 "GCM155R71H104KE02D" 0402 4679.99,3376.38 r270 top value=0.1uF
C174 "GCM155R71H104KE02D" 0402 4054.99,3376.38 r270 top value=0.1uF
C175 "GCM155R71H104KE02D" 0402 4758.99,3376.38 r270 top value=0.1uF
C176 "GCM155R71H104KE02D" 0402 4132.99,3376.38 r270 top value=0.1uF
C177 "GCM155R71H104KE02D" 0402 4835.58,3378.62 r270 top value=0.1uF
C178 "GCM155R71H104KE02D" 0402 4210.99,3376.38 r270 top value=0.1uF
C179 "GCM188R71C474KA55D" 0603 3862.36,3095 r90 top value=0.47uF
C180 "GCM155R71H104KE02D" 0402 4912.99,3376.38 r270 top value=0.1uF
C181 "GCM155R71H104KE02D" 0402 4288.99,3376.38 r270 top value=0.1uF
C182 "GCM155R71H104KE02D" 0402 4990.99,3376.38 r270 top value=0.1uF
C183 "GCM155R71H104KE02D" 0402 4366.99,3376.38 r270 top value=0.1uF
C184 "GCM155R71H104KE02D" 0402 5068.99,3376.38 r270 top value=0.1uF
C185 "GCM155R71H104KE02D" 0402 4444.99,3376.38 r270 top value=0.1uF
C186 "GCM155R71H104KE02D" 0402 5159.99,3376.38 r270 top value=0.1uF
C187 "GCM155R71H104KE02D" 0402 4522.99,3376.38 r270 top value=0.1uF
C188 "GCM155R71H104KE02D" 0402 5261.04,3376.38 r270 top value=0.1uF
C189 "GCM155R71H104KE02D" 0402 4600.99,3376.38 r270 top value=0.1uF
C190 "GCM188R71C474KA55D" 0603 4516.77,2365 r0 bottom value=0.47uF
C191 "GCM188R71C474KA55D" 0603 4271.77,2875 r270 bottom value=0.47uF
C192 "GCM188R71C474KA55D" 0603 4516.77,2365 r0 top value=0.47uF
C193 "GCM188R71C474KA55D" 0603 4271.77,2873.5 r270 top value=0.47uF
C194 "GCM188R71C474KA55D" 0603 4336.77,2807.05 r270 bottom value=0.47uF
C195 "GCM188R71C474KA55D" 0603 4581.77,2300 r0 bottom value=0.47uF
C196 "GCM188R71C474KA55D" 0603 4581.77,2300 r0 top value=0.47uF
C197 "GCM188R71C474KA55D" 0603 4336.77,2810 r270 top value=0.47uF
C198 "GCM188R71C474KA55D" 0603 4646.77,2365 r0 top value=0.47uF
C199 "GCM188R71C474KA55D" 0603 4271.77,2740 r270 bottom value=0.47uF
C200 "GCM188R71C474KA55D" 0603 4271.77,2740 r270 top value=0.47uF
C201 "GCM188R71C474KA55D" 0603 4646.77,2365 r0 bottom value=0.47uF
C202 "GCM188R71C474KA55D" 0603 4711.77,2300 r0 bottom value=0.47uF
C203 "GCM188R71C474KA55D" 0603 4711.77,2299.49 r0 top value=0.47uF
C204 "GCM188R71C474KA55D" 0603 4336.77,2675 r270 bottom value=0.47uF
C205 "GCM188R71C474KA55D" 0603 4336.77,2673.5 r270 top value=0.47uF
C206 "GCM188R71C474KA55D" 0603 4783.27,2365 r0 bottom value=0.47uF
C207 "GCM188R71C474KA55D" 0603 4781.77,2365 r0 top value=0.47uF
C208 "GCM188R71C474KA55D" 0603 4275,2610 r270 bottom value=0.47uF
C209 "GCM188R71C474KA55D" 0603 4271.77,2610 r270 top value=0.47uF
C210 "GCM188R71C474KA55D" 0603 4846.77,2300 r0 bottom value=0.47uF
C211 "GCM188R71C474KA55D" 0603 4848.27,2300 r0 top value=0.47uF
C212 "GCM188R71C474KA55D" 0603 4337.36,2545 r270 bottom value=0.47uF
C213 "GCM188R71C474KA55D" 0603 4336.77,2543.5 r270 top value=0.47uF
C214 "GCM188R71C474KA55D" 0603 4921.77,2365 r0 bottom value=0.47uF
C215 "GCM188R71C474KA55D" 0603 4920.28,2365 r0 top value=0.47uF
C216 "GCM188R71C474KA55D" 0603 4275,2481.5 r270 bottom value=0.47uF
C217 "GCM188R71C474KA55D" 0603 4271.77,2480 r270 top value=0.47uF
C218 "GCM188R71C474KA55D" 0603 5017.36,2400 r90 bottom value=0.47uF
C219 "GCM188R71C474KA55D" 0603 5022.36,2408.5 r90 top value=0.47uF
C220 "GCM188R71C474KA55D" 0603 4446.77,2300 r0 bottom value=0.47uF
C221 "GCM188R71C474KA55D" 0603 4446.77,2300 r0 top value=0.47uF
C222 "GCM188R71C474KA55D" 0603 5082.36,2470 r90 top value=0.47uF
C223 "GCM188R71C474KA55D" 0603 5082.36,2470 r90 bottom value=0.47uF
D1 "150060VS75000" WL-SMCW_GREEN 1780,2510 r90 top value=Green
D2 "SMAJ70A" SMA 1193.74,2915 r0 bottom value=70V
D3 "SMAJ70A" SMA 4561.1,2915 r0 bottom value=70V
D4 "150060RS75000" WL-SMCW_RED 1930,1115 r180 bottom value=Red
D5 "150060RS75000" WL-SMCW_RED 257.95,1783.75 r180 bottom value=Red
D6 "ESDALC6V1-1U2" ST0201 1309.41,3487.68 r270 bottom value=6.1V
D7 "ESDALC6V1-1U2" ST0201 684.41,3487.62 r270 bottom value=6.1V
D8 "CDSOD323-T08SC" SOD-323-Bi 6425,3260 r180 top value=8V
D9 "CDSOD323-T08SC" SOD-323-Bi 3210,3400 r180 top value=8V
D10 "150060RS75000" WL-SMCW_RED 1930,1531.84 r180 bottom value=Red
D11 "150060RS75000" WL-SMCW_RED 257.95,2443.75 r180 bottom value=Red
D12 "ESDALC6V1-1U2" ST0201 4677.14,3487.68 r270 bottom value=6.1V
D13 "ESDALC6V1-1U2" ST0201 4052.14,3487.62 r270 bottom value=6.1V
D14 "ESDALC6V1-1U2" ST0201 4756.14,3487.69 r270 bottom value=6.1V
D15 "ESDALC6V1-1U2" ST0201 4130.14,3487.69 r270 bottom value=6.1V
D16 "150060RS75000" WL-SMCW_RED 1930,1921.22 r180 bottom value=Red
D17 "150060RS75000" WL-SMCW_RED 815,1135 r180 bottom value=Red
D18 "ESDALC6V1-1U2" ST0201 4832.73,3490 r270 bottom value=6.1V
D19 "ESDALC6V1-1U2" ST0201 4208.14,3487.7 r270 bottom value=6.1V
D20 "ESDALC6V1-1U2" ST0201 4910.14,3487.7 r270 bottom value=6.1V
D21 "ESDALC6V1-1U2" ST0201 4286.14,3487.7 r270 bottom value=6.1V
D22 "150060RS75000" WL-SMCW_RED 2468.66,1120 r180 bottom value=Red
D23 "150060RS75000" WL-SMCW_RED 818.66,1530 r180 bottom value=Red
D24 "ESDALC6V1-1U2" ST0201 4988.14,3487.7 r270 bottom value=6.1V
D25 "ESDALC6V1-1U2" ST0201 4364.14,3487.7 r270 bottom value=6.1V
D26 "ESDALC6V1-1U2" ST0201 5066.14,3487.7 r270 bottom value=6.1V
D27 "ESDALC6V1-1U2" ST0201 4442.15,3487.7 r270 bottom value=6.1V
D28 "150060RS75000" WL-SMCW_RED 2460,1545 r180 bottom value=Red
D29 "150060RS75000" WL-SMCW_RED 818.66,1925 r180 bottom value=Red
D30 "ESDALC6V1-1U2" ST0201 5157.14,3487.7 r270 bottom value=6.1V
D31 "ESDALC6V1-1U2" ST0201 4520.14,3487.7 r270 bottom value=6.1V
D32 "ESDALC6V1-1U2" ST0201 5259.14,3487.7 r270 bottom value=6.1V
D33 "ESDALC6V1-1U2" ST0201 4598.14,3487.7 r270 bottom value=6.1V
D34 "150060RS75000" WL-SMCW_RED 2455,1945 r180 bottom value=Red
D35 "150060RS75000" WL-SMCW_RED 1379.72,1130 r180 bottom value=Red
D36 "ESDALC6V1-1U2" ST0201 1388.41,3487.69 r270 bottom value=6.1V
D37 "ESDALC6V1-1U2" ST0201 762.41,3487.69 r270 bottom value=6.1V
D38 "ESDALC6V1-1U2" ST0201 1465,3489.94 r270 bottom value=6.1V
D39 "ESDALC6V1-1U2" ST0201 840.41,3487.7 r270 bottom value=6.1V
D40 "ESDALC6V1-1U2" ST0201 1542.41,3487.7 r270 bottom value=6.1V
D41 "150060RS75000" WL-SMCW_RED 3020,1220 r180 bottom value=Red
D42 "150060RS75000" WL-SMCW_RED 1379.71,1535 r180 bottom value=Red
D43 "ESDALC6V1-1U2" ST0201 918.41,3487.7 r270 bottom value=6.1V
D44 "SMCJ70A" SMC_265 916.73,165 r0 bottom value=70V
D45 "150060VS75000" WL-SMCW_GREEN 5147.36,2510 r90 top value=Green
D46 "ESDALC6V1-1U2" ST0201 1620.41,3487.7 r270 bottom value=6.1V
D47 "150060RS75000" WL-SMCW_RED 3015,1850 r180 bottom value=Red
D48 "150060RS75000" WL-SMCW_RED 1379.72,1930 r180 bottom value=Red
D49 "ESDALC6V1-1U2" ST0201 996.41,3487.7 r270 bottom value=6.1V
D50 "ESDALC6V1-1U2" ST0201 1698.41,3487.7 r270 bottom value=6.1V
D51 "ESDALC6V1-1U2" ST0201 1074.41,3487.7 r270 bottom value=6.1V
D52 "ESDALC6V1-1U2" ST0201 1789.41,3487.7 r270 bottom value=6.1V
D53 "ESDALC6V1-1U2" ST0201 1152.41,3487.7 r270 bottom value=6.1V
D54 "ESDALC6V1-1U2" ST0201 1891.41,3487.7 r270 bottom value=6.1V
D55 "ESDALC6V1-1U2" ST0201 1230.41,3487.7 r270 bottom value=6.1V
D56 "SMCJ70A" SMC_265 4284.09,165 r0 bottom value=70V
D57 "150060RS75000" WL-SMCW_RED 5297.36,1115 r180 bottom value=Red
D58 "150060RS75000" WL-SMCW_RED 3630,1785 r180 bottom value=Red
D59 "150060RS75000" WL-SMCW_RED 5297.36,1531.84 r180 bottom value=Red
D60 "150060RS75000" WL-SMCW_RED 3625.31,2443.75 r180 bottom value=Red
D61 "150060RS75000" WL-SMCW_RED 5297.36,1921.22 r180 bottom value=Red
D62 "150060RS75000" WL-SMCW_RED 4180,1135 r180 bottom value=Red
D63 "150060RS75000" WL-SMCW_RED 5836.02,1120 r180 bottom value=Red
D64 "150060RS75000" WL-SMCW_RED 4185,1530 r180 bottom value=Red
D65 "150060RS75000" WL-SMCW_RED 5827.36,1545 r180 bottom value=Red
D66 "150060RS75000" WL-SMCW_RED 4186.02,1925 r180 bottom value=Red
D67 "150060RS75000" WL-SMCW_RED 5822.36,1945 r180 bottom value=Red
D68 "150060RS75000" WL-SMCW_RED 4747.08,1130 r180 bottom value=Red
D69 "150060RS75000" WL-SMCW_RED 6387.36,1220 r180 bottom value=Red
D70 "150060RS75000" WL-SMCW_RED 4747.08,1535 r180 bottom value=Red
D71 "150060RS75000" WL-SMCW_RED 6382.36,1850 r180 bottom value=Red
D72 "150060RS75000" WL-SMCW_RED 4747.09,1930 r180 bottom value=Red
FID1 "Fiducial" Fiducial10-30 6715,3340 r0 top
FID2 "Fiducial" Fiducial10-30 6615,540 r0 top
FID3 "Fiducial" Fiducial10-30 139.69,410 r0 top
FID4 "Fiducial" Fiducial10-30 6715,3340 r180 bottom
FID5 "Fiducial" Fiducial10-30 6615,540 r180 bottom
FID6 "Fiducial" Fiducial10-30 139.69,410 r180 bottom
J1 "61300411121" WURTH_61300411121 420,3650 r0 top
J2 "61302421821" FP-SSQ-112-04-G-D_CONN_RCPT24-MFG 6976.41,1958.96 r270 bottom
J3 "61300211121" WURTH_61300211121 270,3090 r270 top
J4 "TSW-120-07-G-S" TSW-120-07-G-S 1620,630 r0 top
J5 "61300211121" WURTH_61300211121 7451.24,3631.97 r0 top
J6 "61300821121" FP-61300821121_HDR8-MFG 420,3465 r0 top
J7 "61302421821" FP-SSQ-112-04-G-D_CONN_RCPT24-MFG 6976.41,633.49 r270 bottom
J8 "61300821121" FP-61300821121_HDR8-MFG 7147.24,2891.97 r180 top
J9 "SSQ-112-04-G-D" FP-SSQ-112-04-G-D_CONN_RCPT24-MFG 1339.41,3650 r0 top
J10 "705550056" FP-705550056_HDR22-MFG 4987.36,277.36 r0 top
J11 "SSQ-112-04-G-D" FP-SSQ-112-04-G-D_CONN_RCPT24-MFG 4706.77,3650 r0 top
J12 "TSW-105-08-L-D-RA" FP-TSW-105-08-L-D-RA_HDR10-MFG 7142.24,3945 r180 top
J13 "61300511121" Wurth_61300511121 3800,3685 r180 top
J14 "61300821121" FP-61300821121_HDR8-MFG 3787.36,3465 r0 top
J15 "613020143121" TSW-120-07-G-S 7520,1215 r270 bottom
J16 "61300211121" WURTH_61300211121 3637.36,3090 r270 top
J17 "61300411121" WURTH_61300411121 420,3250 r0 top
J18 "TSW-120-07-G-S" TSW-120-07-G-S 4987.36,630 r0 top
J19 "61300411121" WURTH_61300411121 3787.36,3250 r0 top
J20 "61300511121" Wurth_61300511121 7146.24,2711.97 r180 top
J21 "705550056" FP-705550056_HDR22-MFG 1620,277.36 r0 top
J26 "61300311121" WURTH_61300311121 5555,2780 r90 top
J27 "61300311121" WURTH_61300311121 2615,2410 r270 top
J28 "61300311121" WURTH_61300311121 2165,2745 r90 top
J29 "61300311121" WURTH_61300311121 6145,2475 r90 top
J30 "70551-0038" Molex_70551-0038 6460,3495 r90 top
J31 "70551-0038" Molex_70551-0038 3105,3495 r90 top
J32 "61300211121" WURTH_61300211121 6370,3380 r180 top
J33 "61300211121" WURTH_61300211121 3220,3280 r180 top
LBL1 "THT-14-423-10" Label_650x200 3405,170 r180 top
Logo1 "CE Mark" CE_Mark_5mm 3585,500 r180 top
LOGO2 "Pb-Free Symbol" Pb-Free_Overlay_Small 6340,150 r90 top (schematic designator Logo2)
Logo3 "FCC disclaimer" FCC_disclaimer 3425,1470 r90 top
Logo4 "DANGER HIGH VOLTAGE" IEC_HighVoltage_Small 6425,395 r0 top
Logo5 "WEEE logo" WEEE_Minimum 3065,455 r90 top
Q1 "BJT_NPN_C2B1E3" DPAK 2330,3395 r0 top value="150 V"
Q2 "FCX690BTA" SOT-89-3 2140,1120.62 r180 bottom value="45 V"
Q3 "FCX690BTA" SOT-89-3 462.95,1784.15 r180 bottom value="45 V"
Q4 "FCX690BTA" SOT-89-3 462.95,2448.75 r180 bottom value="45 V"
Q5 "FCX690BTA" SOT-89-3 2140,1545.62 r180 bottom value="45 V"
Q6 "FCX690BTA" SOT-89-3 2140,1935 r180 bottom value="45 V"
Q7 "FCX690BTA" SOT-89-3 1045.43,1140.39 r180 bottom value="45 V"
Q8 "FCX690BTA" SOT-89-3 2680,1135.62 r180 bottom value="45 V"
Q9 "FCX690BTA" SOT-89-3 1045.43,1535.39 r180 bottom value="45 V"
Q10 "FCX690BTA" SOT-89-3 2675,1545 r180 bottom value="45 V"
Q11 "FCX690BTA" SOT-89-3 1045.43,1925 r180 bottom value="45 V"
Q12 "FCX690BTA" SOT-89-3 2670,1950.62 r180 bottom value="45 V"
Q13 "FCX690BTA" SOT-89-3 1585,1145.39 r180 bottom value="45 V"
Q14 "FCX690BTA" SOT-89-3 3218.07,1230 r180 bottom value="45 V"
Q15 "FCX690BTA" SOT-89-3 1579.57,1545.69 r180 bottom value="45 V"
Q16 "FCX690BTA" SOT-89-3 3218.07,1865 r180 bottom value="45 V"
Q17 "FCX690BTA" SOT-89-3 1580,1940.39 r180 bottom value="45 V"
Q37 "BSS223PWH6327" SOT-323 7438.24,2955.97 r270 top value=-20V
Q38 "ISOM8110DFG" DFG0004A-MFG 7485.95,3322.5 r270 top value=80V
Q39 "BJT_NPN_C2B1E3" DPAK 5697.36,3395 r0 top value="150 V"
Q40 "FCX690BTA" SOT-89-3 5507.36,1120.62 r180 bottom value="45 V"
Q41 "FCX690BTA" SOT-89-3 3830.31,1784.15 r180 bottom value="45 V"
Q42 "FCX690BTA" SOT-89-3 3830.31,2448.75 r180 bottom value="45 V"
Q43 "FCX690BTA" SOT-89-3 5507.36,1545.62 r180 bottom value="45 V"
Q44 "FCX690BTA" SOT-89-3 5507.36,1935 r180 bottom value="45 V"
Q45 "FCX690BTA" SOT-89-3 4412.8,1140.39 r180 bottom value="45 V"
Q46 "FCX690BTA" SOT-89-3 6047.36,1135.62 r180 bottom value="45 V"
Q47 "FCX690BTA" SOT-89-3 4420,1535 r180 bottom value="45 V"
Q48 "FCX690BTA" SOT-89-3 6042.36,1545 r180 bottom value="45 V"
Q49 "FCX690BTA" SOT-89-3 4412.8,1925 r180 bottom value="45 V"
Q50 "FCX690BTA" SOT-89-3 6037.36,1950.62 r180 bottom value="45 V"
Q51 "FCX690BTA" SOT-89-3 4952.36,1145.39 r180 bottom value="45 V"
Q52 "FCX690BTA" SOT-89-3 6585.43,1230 r180 bottom value="45 V"
Q53 "FCX690BTA" SOT-89-3 4946.93,1545.69 r180 bottom value="45 V"
Q54 "FCX690BTA" SOT-89-3 6585.43,1865 r180 bottom value="45 V"
Q55 "FCX690BTA" SOT-89-3 4947.36,1940.39 r180 bottom value="45 V"
R1 "RC0603JR-070RL" 0603 734.41,2740 r270 bottom value=0
R2 "RC0603JR-070RL" 0603 734.41,2875 r270 bottom value=0
R3 "RC0603JR-070RL" 0603 799.41,2672.01 r270 top value=0
R4 "RC0603JR-070RL" 0603 799.41,2805 r270 top value=0
R5 "RC0603JR-070RL" 0603 799.41,2680 r270 bottom value=0
R6 "RC0603JR-070RL" 0603 799.41,2810 r270 bottom value=0
R7 "RC0603JR-070RL" 0603 734.41,2741.5 r270 top value=0
R8 "RC0603JR-070RL" 0603 734.41,2875 r270 top value=0
R9 "CRCW06030000Z0EA" 0603 1202.64,245 r180 bottom value=0
R10 "RC0603JR-070RL" 0603 4169.41,2670.51 r270 top value=0
R11 "RC0603JR-070RL" 0603 4101.77,2741.5 r270 top value=0
R12 "CRCW0402300RJNED" 0402 1975,1180 r0 bottom value=300
R13 "CRCW0402300RJNED" 0402 342.95,1853.75 r0 bottom value=300
R14 "RC0603JR-070RL" 0603 799.41,2950 r270 bottom value=0
R15 "RC1210FR-0730RL" 1210 1619.57,1930 r90 top value=30.0
R16 "CRCW0402300RJNED" 0402 247.95,2513.75 r0 bottom value=300
R17 "CRCW0402300RJNED" 0402 1975,1598.77 r0 bottom value=300
R18 "RC1210FR-0730RL" 1210 470,1028.75 r90 top value=30.0
R19 "RC1210FR-0730RL" 1210 1369.46,1930 r90 top value=30.0
R20 "CRCW0402300RJNED" 0402 1975,1988.15 r0 bottom value=300
R21 "RC1210FR-0730RL" 1210 280,1028.75 r90 top value=30.0
R22 "RC1210FR-0730RL" 1210 280,1776.25 r90 top value=30.0
R23 "RC1210FR-0730RL" 1210 2179.57,1130 r90 top value=30.0
R24 "CRCW2010100RFKEF" 2010 2205,3600 r180 top value=100
R25 "CRCW2010200RFKEF" 2010 2205,3755 r0 top value=200
R26 "RC1210FR-0730RL" 1210 1929.46,1130 r90 top value=30.0
R27 "RC1210FR-0730RL" 1210 470,1776.25 r90 top value=30.0
R28 "RC1210FR-0730RL" 1210 280,2443.75 r90 top value=30.0
R29 "CRCW080530R0JNEA" 0805_HV 620,2953.5 r0 top value=30
R30 "CRCW06031K00JNEA" 0603 1745,2600 r180 top value=1.0k
R31 "CRCW060310K0FKEA" 0603 1306.12,3373.5 r90 bottom value=10.0k
R32 "CRCW04021K00JNED" 0402 1311.08,3486.38 r270 top value=1.0k
R33 "CRCW060310K0FKEA" 0603 684.41,3373.5 r90 bottom value=10.0k
R34 "CRCW04021K00JNED" 0402 689.41,3486.38 r270 top value=1.0k
R35 "CRCW060310K0FKEA" 0603 1385.78,3373.5 r90 bottom value=10.0k
R36 "CRCW04021K00JNED" 0402 1390.74,3486.38 r270 top value=1.0k
R37 "CRCW060310K0FKEA" 0603 762.08,3373.5 r90 bottom value=10.0k
R38 "CRCW04021K00JNED" 0402 767.08,3486.38 r270 top value=1.0k
R39 "CRCW060310K0FKEA" 0603 1462.04,3375.75 r90 bottom value=10.0k
R40 "CRCW04021K00JNED" 0402 1467,3488.62 r270 top value=1.0k
R41 "CRCW060310K0FKEA" 0603 839.75,3373.5 r90 bottom value=10.0k
R42 "CRCW04021K00JNED" 0402 844.74,3486.38 r270 top value=1.0k
R43 "CRCW060310K0FKEA" 0603 1538.79,3373.5 r90 bottom value=10.0k
R44 "CRCW04021K00JNED" 0402 1543.74,3486.38 r270 top value=1.0k
R45 "CRCW060310K0FKEA" 0603 917.42,3373.5 r90 bottom value=10.0k
R46 "CRCW0603402RFKEA" 0603 395,3080 r0 top value=402
R47 "RC0603JR-070RL" 0603 600,3075 r180 top value=0
R48 "CRCW04021K00JNED" 0402 922.41,3486.38 r270 top value=1.0k
R49 "CRCW060310K0FKEA" 0603 1616.46,3373.5 r90 bottom value=10.0k
R50 "CRCW0603402RFKEA" 0603 398.5,3145 r0 top value=402
R51 "RC0603JR-070RL" 0603 600,3140 r180 top value=0
R52 "CRCW04021K00JNED" 0402 1621.41,3486.38 r270 top value=1.0k
R53 "CRCW060310K0FKEA" 0603 995.09,3373.5 r90 bottom value=10.0k
R54 "CRCW04021K00JNED" 0402 1000.08,3486.38 r270 top value=1.0k
R55 "CRCW060310K0FKEA" 0603 1694.13,3373.5 r90 bottom value=10.0k
R56 "CRCW04021K00JNED" 0402 1699.08,3486.38 r270 top value=1.0k
R57 "CRCW060310K0FKEA" 0603 1072.77,3373.5 r90 bottom value=10.0k
R58 "CRCW04021K00JNED" 0402 1077.74,3486.38 r270 top value=1.0k
R59 "CRCW060310K0FKEA" 0603 1784.48,3373.5 r90 bottom value=10.0k
R60 "CRCW04021K00JNED" 0402 1789.41,3486.38 r270 top value=1.0k
R61 "CRCW060310K0FKEA" 0603 1150.44,3373.5 r90 bottom value=10.0k
R62 "CRCW04021K00JNED" 0402 1155.41,3486.38 r270 top value=1.0k
R63 "CRCW060310K0FKEA" 0603 1886.8,3373.5 r90 bottom value=10.0k
R64 "CRCW04021K00JNED" 0402 1891.74,3486.38 r270 top value=1.0k
R65 "CRCW060310K0FKEA" 0603 1224.41,3375 r90 bottom value=10.0k
R66 "CRCW04021K00JNED" 0402 1233.08,3486.38 r270 top value=1.0k
R67 "RC1210FR-0730RL" 1210 470,2443.75 r90 top value=30.0
R68 "RC0603JR-070RL" 0603 1665,2790 r0 top value=0
R69 "CRCW060351R0JNEA" 0603 2833.35,2493.7 r180 top value=51
R70 "RC0603JR-070RL" 0603 3125,2490 r180 top value=0
R71 "RC0603JR-070RL" 0603 6060,2850 r0 top value=0
R72 "CRCW060351R0JNEA" 0603 5780,2855 r0 top value=51
R73 "ERJ-3EKF1001V" 0603 2733.35,2528.7 r270 top value=1.00k
R74 "ERJ-3EKF1001V" 0603 5665,2820 r90 top value=1.00k
R75 "CRCW060351R0JNEA" 0603 2833.35,2563.7 r180 top value=51
R76 "RC0603JR-070RL" 0603 3128.35,2563.7 r180 top value=0
R77 "RC0603JR-070RL" 0603 6060,2780 r0 top value=0
R78 "CRCW060351R0JNEA" 0603 5780,2780 r0 top value=51
R79 "RC0603JR-070RL" 0603 4169.41,2803.5 r270 top value=0
R80 "RC0603JR-070RL" 0603 6465,2578.5 r270 top value=0
R81 "CRCW060351R0JNEA" 0603 6365,2485 r180 top value=51
R82 "CRCW060351R0JNEA" 0603 2375,2855 r0 top value=51
R83 "RC0603JR-070RL" 0603 2510,2920 r0 top value=0
R84 "RC0603JR-070RL" 0603 4101.77,2875 r270 top value=0
R85 "ERJ-3EKF1001V" 0603 6260,2450 r90 top value=1.00k
R86 "ERJ-3EKF1001V" 0603 2275,2820 r90 top value=1.00k
R87 "RC0603JR-070RL" 0603 4166.77,2680 r270 bottom value=0
R88 "RC0603JR-070RL" 0603 6565,2575 r270 top value=0
R89 "CRCW060351R0JNEA" 0603 6365,2400 r180 top value=51
R90 "CRCW060351R0JNEA" 0603 2373.19,2790 r0 top value=51
R91 "RC0603JR-070RL" 0603 2511.5,2720 r0 top value=0
R92 "RC0603JR-070RL" 0603 4101.77,2738.54 r270 bottom value=0
R93 "ERA-3AEB101V" 0603 1572.5,765 r90 top value=100
R94 "ERA-3AEB101V" 0603 765,765 r90 top value=100
R95 "CRCW0402300RJNED" 0402 853.78,1203.76 r0 bottom value=300
R96 "RC1210FR-0730RL" 1210 1929.46,1540 r90 top value=30.0
R97 "CRCW06031K00JNEA" 0603 1845,945 r90 bottom value=1.0k
R98 "CRCW06031K00JNEA" 0603 207.95,1538.75 r90 bottom value=1.0k
R99 "RC1210FR-0730RL" 1210 2179.57,1540 r90 top value=30.0
R100 "RC1210FR-0730RL" 1210 1035.6,1140 r90 top value=30.0
R101 "RC1210FR-0730RL" 1210 785.49,1140 r90 top value=30.0
R102 "RC1210FR-0730RL" 1210 2179.57,1930 r90 top value=30.0
R103 "RC1210FR-0730RL" 1210 1929.46,1930 r90 top value=30.0
R104 "RC1210FR-0730RL" 1210 2469.46,1130 r90 top value=30.0
R105 "RC1210FR-0730RL" 1210 1034.57,1530 r90 top value=30.0
R106 "CRCW0402300RJNED" 0402 2550,1190 r0 bottom value=300
R107 "CRCW0402300RJNED" 0402 853.78,1598.76 r0 bottom value=300
R108 "RC1210FR-0730RL" 1210 784.46,1530 r90 top value=30.0
R109 "RC1210FR-0730RL" 1210 2719.57,1130 r90 top value=30.0
R110 "ERA-3AEB101V" 0603 1673.44,765 r90 top value=100
R111 "ERA-3AEB101V" 0603 865.94,765 r90 top value=100
R112 "RC1210FR-0730RL" 1210 2464.46,1540 r90 top value=30.0
R113 "RC1210FR-0730RL" 1210 1029.57,1920 r90 top value=30.0
R114 "CRCW06031K00JNEA" 0603 1845,1340 r90 bottom value=1.0k
R115 "CRCW06031K00JNEA" 0603 207.95,2257.26 r90 bottom value=1.0k
R116 "RC1210FR-0730RL" 1210 779.46,1920 r90 top value=30.0
R117 "RC1210FR-0730RL" 1210 2714.57,1540 r90 top value=30.0
R118 "RC1210FR-0730RL" 1210 2709.57,1945 r90 top value=30.0
R119 "RC1210FR-0730RL" 1210 1624.57,1140 r90 top value=30.0
R120 "RC1210FR-0730RL" 1210 1374.46,1140 r90 top value=30.0
R121 "RC1210FR-0730RL" 1210 2459.46,1945 r90 top value=30.0
R122 "RC1210FR-0730RL" 1210 3209.57,1235 r90 top value=30.0
R123 "CRCW0402300RJNED" 0402 2551.38,1610 r0 bottom value=300
R124 "CRCW0402300RJNED" 0402 855,1995 r0 bottom value=300
R125 "RC1210FR-0730RL" 1210 1374.46,1540 r90 top value=30.0
R126 "RC1210FR-0730RL" 1210 1624.57,1540 r90 top value=30.0
R127 "RC1210FR-0730RL" 1210 3020,1235 r90 top value=30.0
R128 "ERA-3AEB101V" 0603 1774.38,765 r90 top value=100
R129 "ERA-3AEB101V" 0603 966.88,765 r90 top value=100
R130 "RC1210FR-0730RL" 1210 3020,1865 r90 top value=30.0
R131 "RC1210FR-0730RL" 1210 3209.57,1865 r90 top value=30.0
R132 "CRCW06031K00JNEA" 0603 1845,1746.5 r90 bottom value=1.0k
R133 "CRCW06031K00JNEA" 0603 685,945 r90 bottom value=1.0k
R134 "CRCW0402300RJNED" 0402 2533.62,2010 r0 bottom value=300
R135 "CRCW0402300RJNED" 0402 1425,1198.54 r0 bottom value=300
R136 "CRCW0402300RJNED" 0402 3051.38,1290 r0 bottom value=300
R137 "CRCW0402300RJNED" 0402 1425,1610 r0 bottom value=300
R138 "CRCW0402300RJNED" 0402 3040,1915 r0 bottom value=300
R139 "CRCW0402300RJNED" 0402 1425,1995 r0 bottom value=300
R140 "CRCW06031K00JNEA" 0603 7389.24,3078.97 r90 top value=1.0k
R141 "CRCW0603100RJNEA" 0603 7462.24,3078.97 r90 top value=100
R142 "CRCW06031K00JNEA" 0603 7460,3510 r180 top value=1.0k
R143 "CRCW0603100KJNEA" 0603 5027.36,3025 r180 top value=100k
R144 "ERA-3AEB101V" 0603 1875.31,765 r90 top value=100
R145 "ERA-3AEB101V" 0603 1067.81,765 r90 top value=100
R146 "CRCW0603100KJNEA" 0603 3735,3605 r180 bottom value=100k
R147 "Resistor" 0603 7137.74,3641.97 r180 top value=100k
R148 "CRCW06031K00JNEA" 0603 2385,945 r90 bottom value=1.0k
R149 "CRCW06031K00JNEA" 0603 700,1326.5 r90 bottom value=1.0k
R150 "RC0603JR-070RL" 0603 4166.77,2810 r270 bottom value=0
R151 "CRCW2010100RFKEF" 2010 5572.36,3600 r180 top value=100
R152 "CRCW2010200RFKEF" 2010 5572.36,3755 r0 top value=200
R153 "RC0603JR-070RL" 0603 1660,3025 r0 top value=0
R154 "RC0603JR-070RL" 0603 4101.77,2875 r270 bottom value=0
R155 "RC0603JR-070RL" 0603 5032.36,2790 r0 top value=0
R156 "CRCW080530R0JNEA" 0805_HV 3990,2955 r0 top value=30
R157 "CRCW06031K00JNEA" 0603 5112.36,2600 r180 top value=1.0k
R158 "CRCW060310K0FKEA" 0603 4671.12,3373.5 r90 bottom value=10.0k
R159 "CRCW04021K00JNED" 0402 4676.66,3486.38 r270 top value=1.0k
R160 "ERA-3AEB101V" 0603 1976.25,765 r90 top value=100
R161 "ERA-3AEB101V" 0603 1168.75,765 r90 top value=100
R162 "CRCW060310K0FKEA" 0603 4049.41,3373.5 r90 bottom value=10.0k
R163 "CRCW04021K00JNED" 0402 4054.41,3486.38 r270 top value=1.0k
R164 "CRCW06031K00JNEA" 0603 2385,1350 r90 bottom value=1.0k
R165 "CRCW06031K00JNEA" 0603 700,1726.5 r90 bottom value=1.0k
R166 "CRCW060310K0FKEA" 0603 4750.78,3373.5 r90 bottom value=10.0k
R167 "CRCW04021K00JNED" 0402 4756.32,3486.38 r270 top value=1.0k
R168 "CRCW060310K0FKEA" 0603 4127.08,3373.5 r90 bottom value=10.0k
R169 "CRCW04021K00JNED" 0402 4132.66,3486.38 r270 top value=1.0k
R170 "CRCW060310K0FKEA" 0603 4827.04,3375.75 r90 bottom value=10.0k
R171 "CRCW04021K00JNED" 0402 4832.58,3488.62 r270 top value=1.0k
R172 "CRCW060310K0FKEA" 0603 4204.75,3373.5 r90 bottom value=10.0k
R173 "CRCW0603402RFKEA" 0603 3762.36,3060 r0 top value=402
R174 "RC0603JR-070RL" 0603 3965,3060 r180 top value=0
R175 "CRCW04021K00JNED" 0402 4210.32,3486.38 r270 top value=1.0k
R176 "ERA-3AEB101V" 0603 2077.19,765 r90 top value=100
R177 "ERA-3AEB101V" 0603 1269.69,765 r90 top value=100
R178 "CRCW060310K0FKEA" 0603 4903.79,3373.5 r90 bottom value=10.0k
R179 "RC0603JR-070RL" 0603 4170,2933.5 r270 top value=0
R180 "CRCW06031K00JNEA" 0603 2390,1755 r90 bottom value=1.0k
R181 "CRCW06031K00JNEA" 0603 1275,945 r90 bottom value=1.0k
R182 "CRCW0603402RFKEA" 0603 3762.36,3125 r0 top value=402
R183 "RC0603JR-070RL" 0603 3965,3130 r180 top value=0
R184 "CRCW04021K00JNED" 0402 4909.32,3486.38 r270 top value=1.0k
R185 "CRCW060310K0FKEA" 0603 4282.42,3373.5 r90 bottom value=10.0k
R186 "CRCW04021K00JNED" 0402 4287.99,3486.38 r270 top value=1.0k
R187 "CRCW060310K0FKEA" 0603 4981.46,3373.5 r90 bottom value=10.0k
R188 "RC0603JR-070RL" 0603 4167.36,2951.34 r270 bottom value=0
R189 "CRCW04020000Z0ED" 0402 1976.38,3295 r0 top value=0
R190 "CRCW04021K00JNED" 0402 4986.99,3486.38 r270 top value=1.0k
R191 "CRCW060310K0FKEA" 0603 4360.09,3373.5 r90 bottom value=10.0k
R192 "CRCW06030000Z0EA" 0603 323.5,435 r0 top value=0
R193 "ERA-3AEB101V" 0603 2178.12,765 r90 top value=100
R194 "ERA-3AEB101V" 0603 1370.62,765 r90 top value=100
R195 "CRCW04020000Z0ED" 0402 5351.38,3290 r180 top value=0
R196 "CRCW060310K0FKEA" 0603 7540,2846.5 r90 top value=10.0k
R197 "CRCW06031K00JNEA" 0603 2940,935 r90 bottom value=1.0k
R198 "CRCW06031K00JNEA" 0603 1275,1330 r90 bottom value=1.0k
R199 "CRCW04021K00JNED" 0402 4365.66,3486.38 r270 top value=1.0k
R200 "CRCW060310K0FKEA" 0603 5059.13,3373.5 r90 bottom value=10.0k
R201 "CRCW04021K00JNED" 0402 5064.66,3486.38 r270 top value=1.0k
R202 "CRCW060310K0FKEA" 0603 4437.77,3373.5 r90 bottom value=10.0k
R203 "CRCW2512100RFKEG" 2512 7350,2365 r90 top value=100
R205 "CRCW2512100RFKEG" 2512 7350,2365 r90 bottom value=100
R207 "CRCW2512100RFKEG" 2512 7350,2052.86 r90 top value=100
R209 "ERA-3AEB101V" 0603 2279.06,765 r90 top value=100
R210 "ERA-3AEB101V" 0603 1471.56,765 r90 top value=100
R211 "CRCW2512100RFKEG" 2512 7350,2053.02 r90 bottom value=100
R213 "CRCW06031K00JNEA" 0603 2935,1560 r90 bottom value=1.0k
R214 "CRCW06031K00JNEA" 0603 1275,1745 r90 bottom value=1.0k
R215 "CRCW2512100RFKEG" 2512 7350,1740.71 r90 top value=100
R217 "CRCW2512100RFKEG" 2512 7350,1741.04 r90 bottom value=100
R219 "CRCW2512100RFKEG" 2512 7350,1428.57 r90 top value=100
R220 "CRCW04021K00JNED" 0402 4443.32,3486.38 r270 top value=1.0k
R222 "CRCW2512100RFKEG" 2512 7350,1429.06 r90 bottom value=100
R223 "CRCW060310K0FKEA" 0603 5149.48,3373.5 r90 bottom value=10.0k
R225 "ERA-3AEB101V" 0603 2380,765 r90 top value=100
R226 "CRCW2512100RFKEG" 2512 7350,1116.43 r90 top value=100
R230 "CRCW2512100RFKEG" 2512 7350,1117.08 r90 bottom value=100
R232 "CRCW2512100RFKEG" 2512 7350,804.29 r90 top value=100
R234 "CRCW2512100RFKEG" 2512 7350,805.1 r90 bottom value=100
R236 "CRCW2512100RFKEG" 2512 7350,492.14 r90 top value=100
R238 "CRCW2512100RFKEG" 2512 7350,493.12 r90 bottom value=100
R240 "CRCW2512100RFKEG" 2512 7350,180 r90 top value=100
R242 "CRCW2512100RFKEG" 2512 7350,181.14 r90 bottom value=100
R282 "CRCW04021K00JNED" 0402 5154.99,3486.38 r270 top value=1.0k
R408 "RC0603JR-070RL" 0603 800,2935 r270 top value=0
R411 "CRCW060310K0FKEA" 0603 4515.44,3373.5 r90 bottom value=10.0k
R412 "CRCW04021K00JNED" 0402 4520.99,3486.38 r270 top value=1.0k
R413 "CRCW060310K0FKEA" 0603 5251.8,3373.5 r90 bottom value=10.0k
R414 "CRCW04021K00JNED" 0402 5257.32,3486.38 r270 top value=1.0k
R415 "CRCW060310K0FKEA" 0603 4589.41,3375 r90 bottom value=10.0k
R416 "CRCW04021K00JNED" 0402 4598.66,3486.38 r270 top value=1.0k
R417 "CRCW06030000Z0EA" 0603 3690.87,435 r0 bottom value=0
R418 "CRCW06030000Z0EA" 0603 4570,245 r180 bottom value=0
R419 "RC1210FR-0730RL" 1210 4986.93,1930 r90 top value=30.0
R420 "RC1210FR-0730RL" 1210 3837.36,1028.75 r90 top value=30.0
R421 "RC1210FR-0730RL" 1210 4736.82,1930 r90 top value=30.0
R422 "RC1210FR-0730RL" 1210 3647.36,1028.75 r90 top value=30.0
R423 "ERA-3AEB101V" 0603 4939.86,765 r90 top value=100
R424 "ERA-3AEB101V" 0603 4132.36,765 r90 top value=100
R425 "CRCW06031K00JNEA" 0603 5212.36,945 r90 bottom value=1.0k
R426 "CRCW06031K00JNEA" 0603 3575.31,1541.71 r90 bottom value=1.0k
R427 "CRCW0402300RJNED" 0402 5345,1180 r0 bottom value=300
R428 "CRCW0402300RJNED" 0402 3710.31,1853.75 r0 bottom value=300
R429 "RC1210FR-0730RL" 1210 3837.36,1776.25 r90 top value=30.0
R430 "RC1210FR-0730RL" 1210 5304.57,1125 r90 top value=30.0
R431 "RC1210FR-0730RL" 1210 5544.57,1130 r90 top value=30.0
